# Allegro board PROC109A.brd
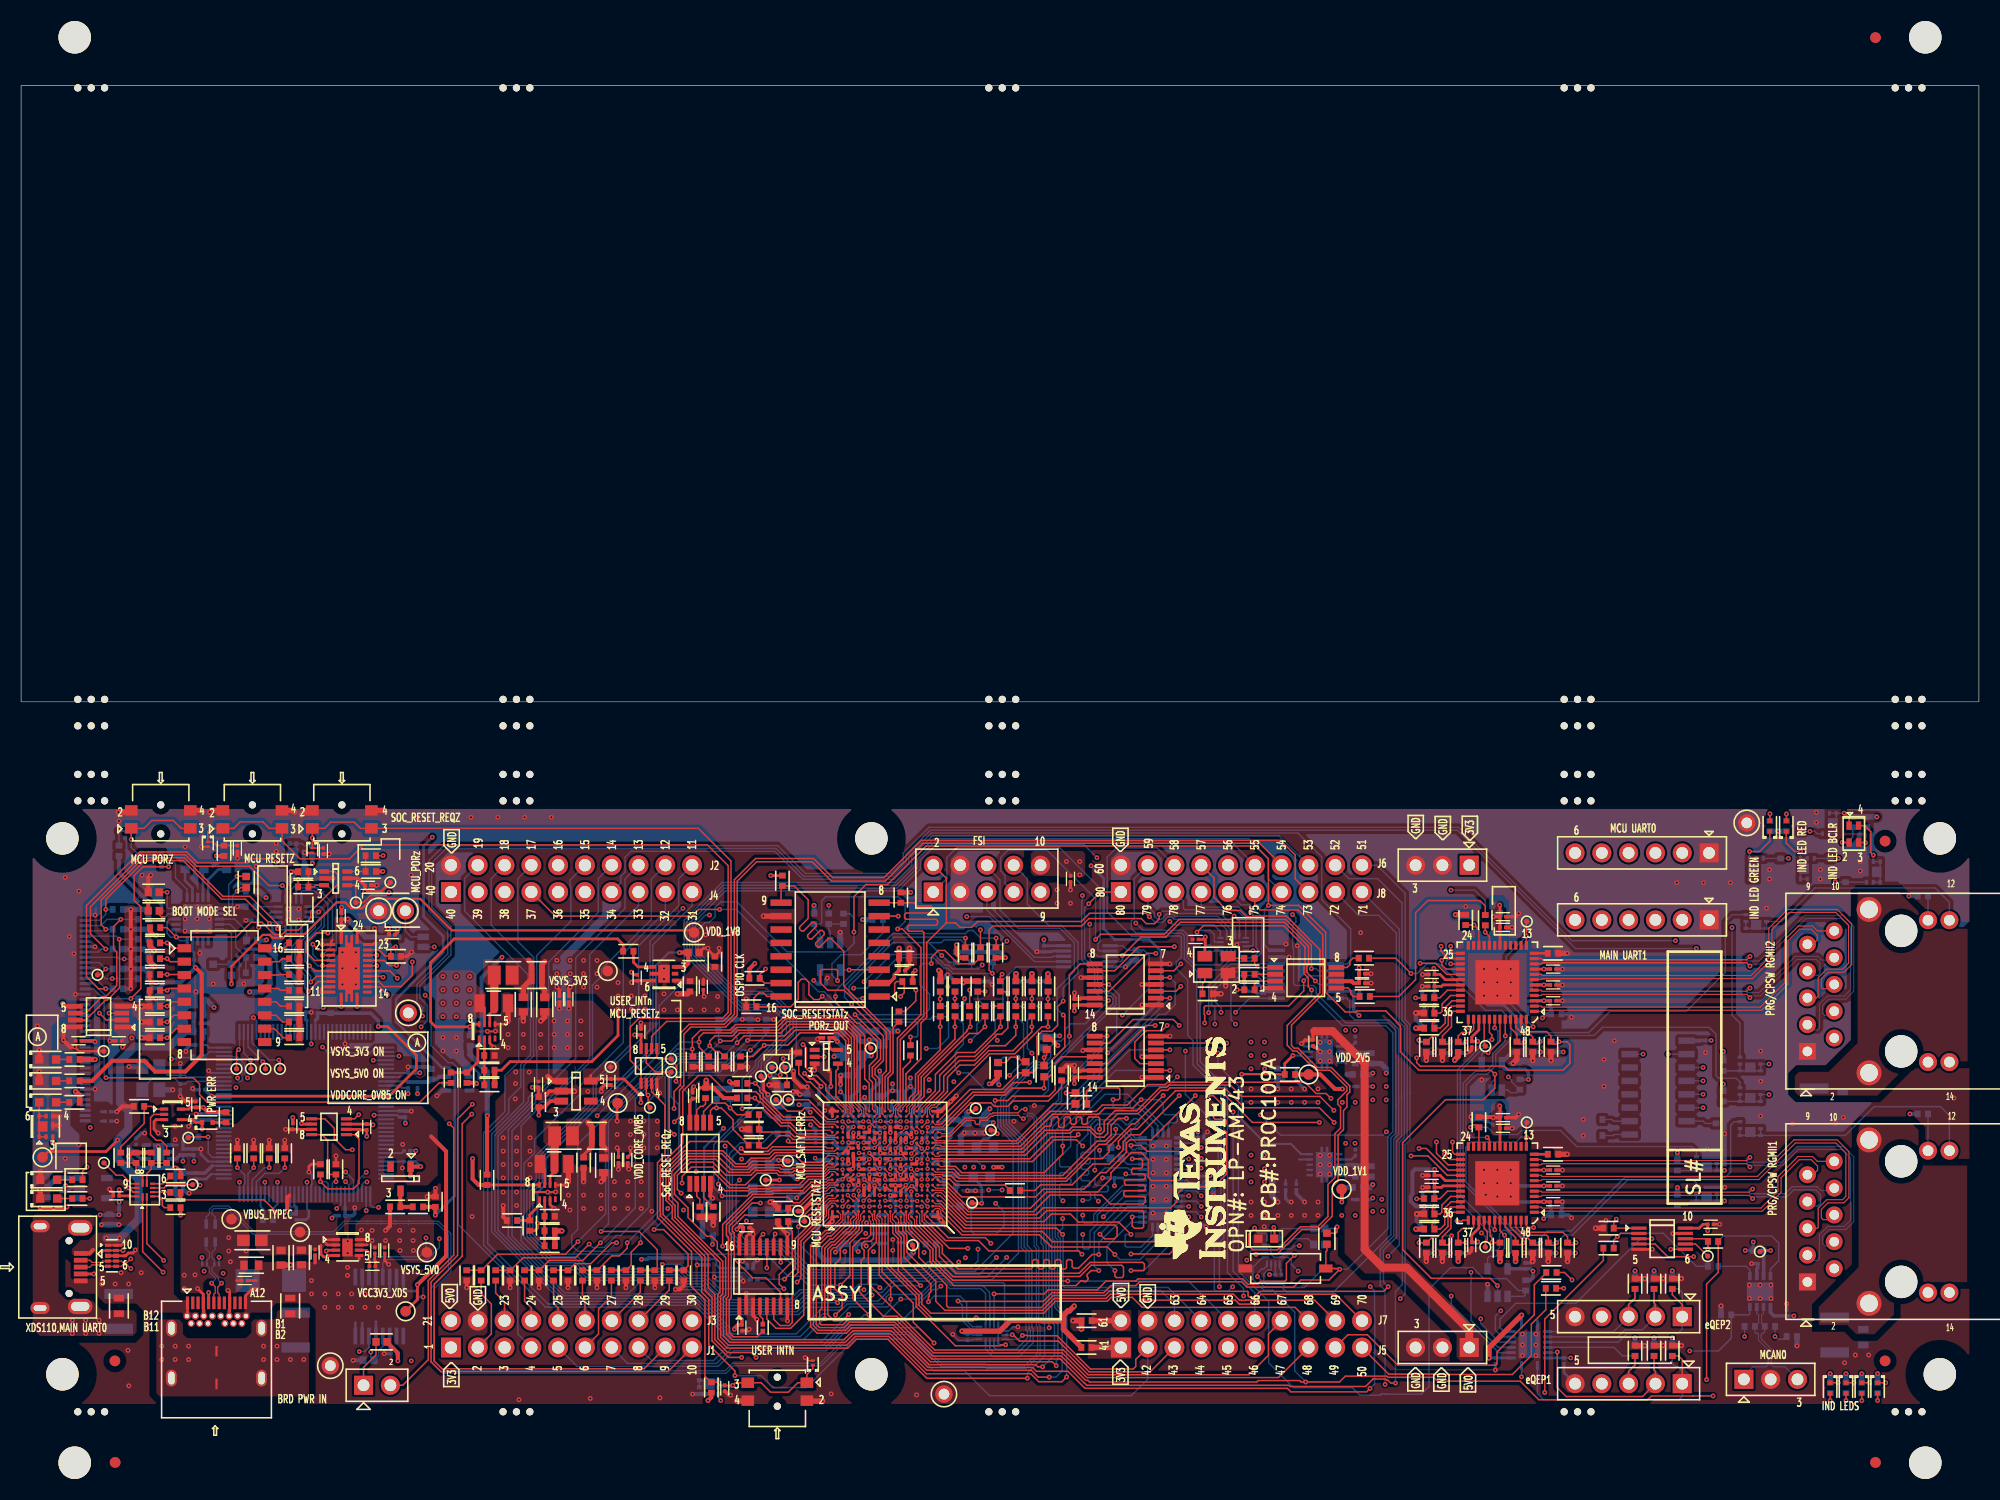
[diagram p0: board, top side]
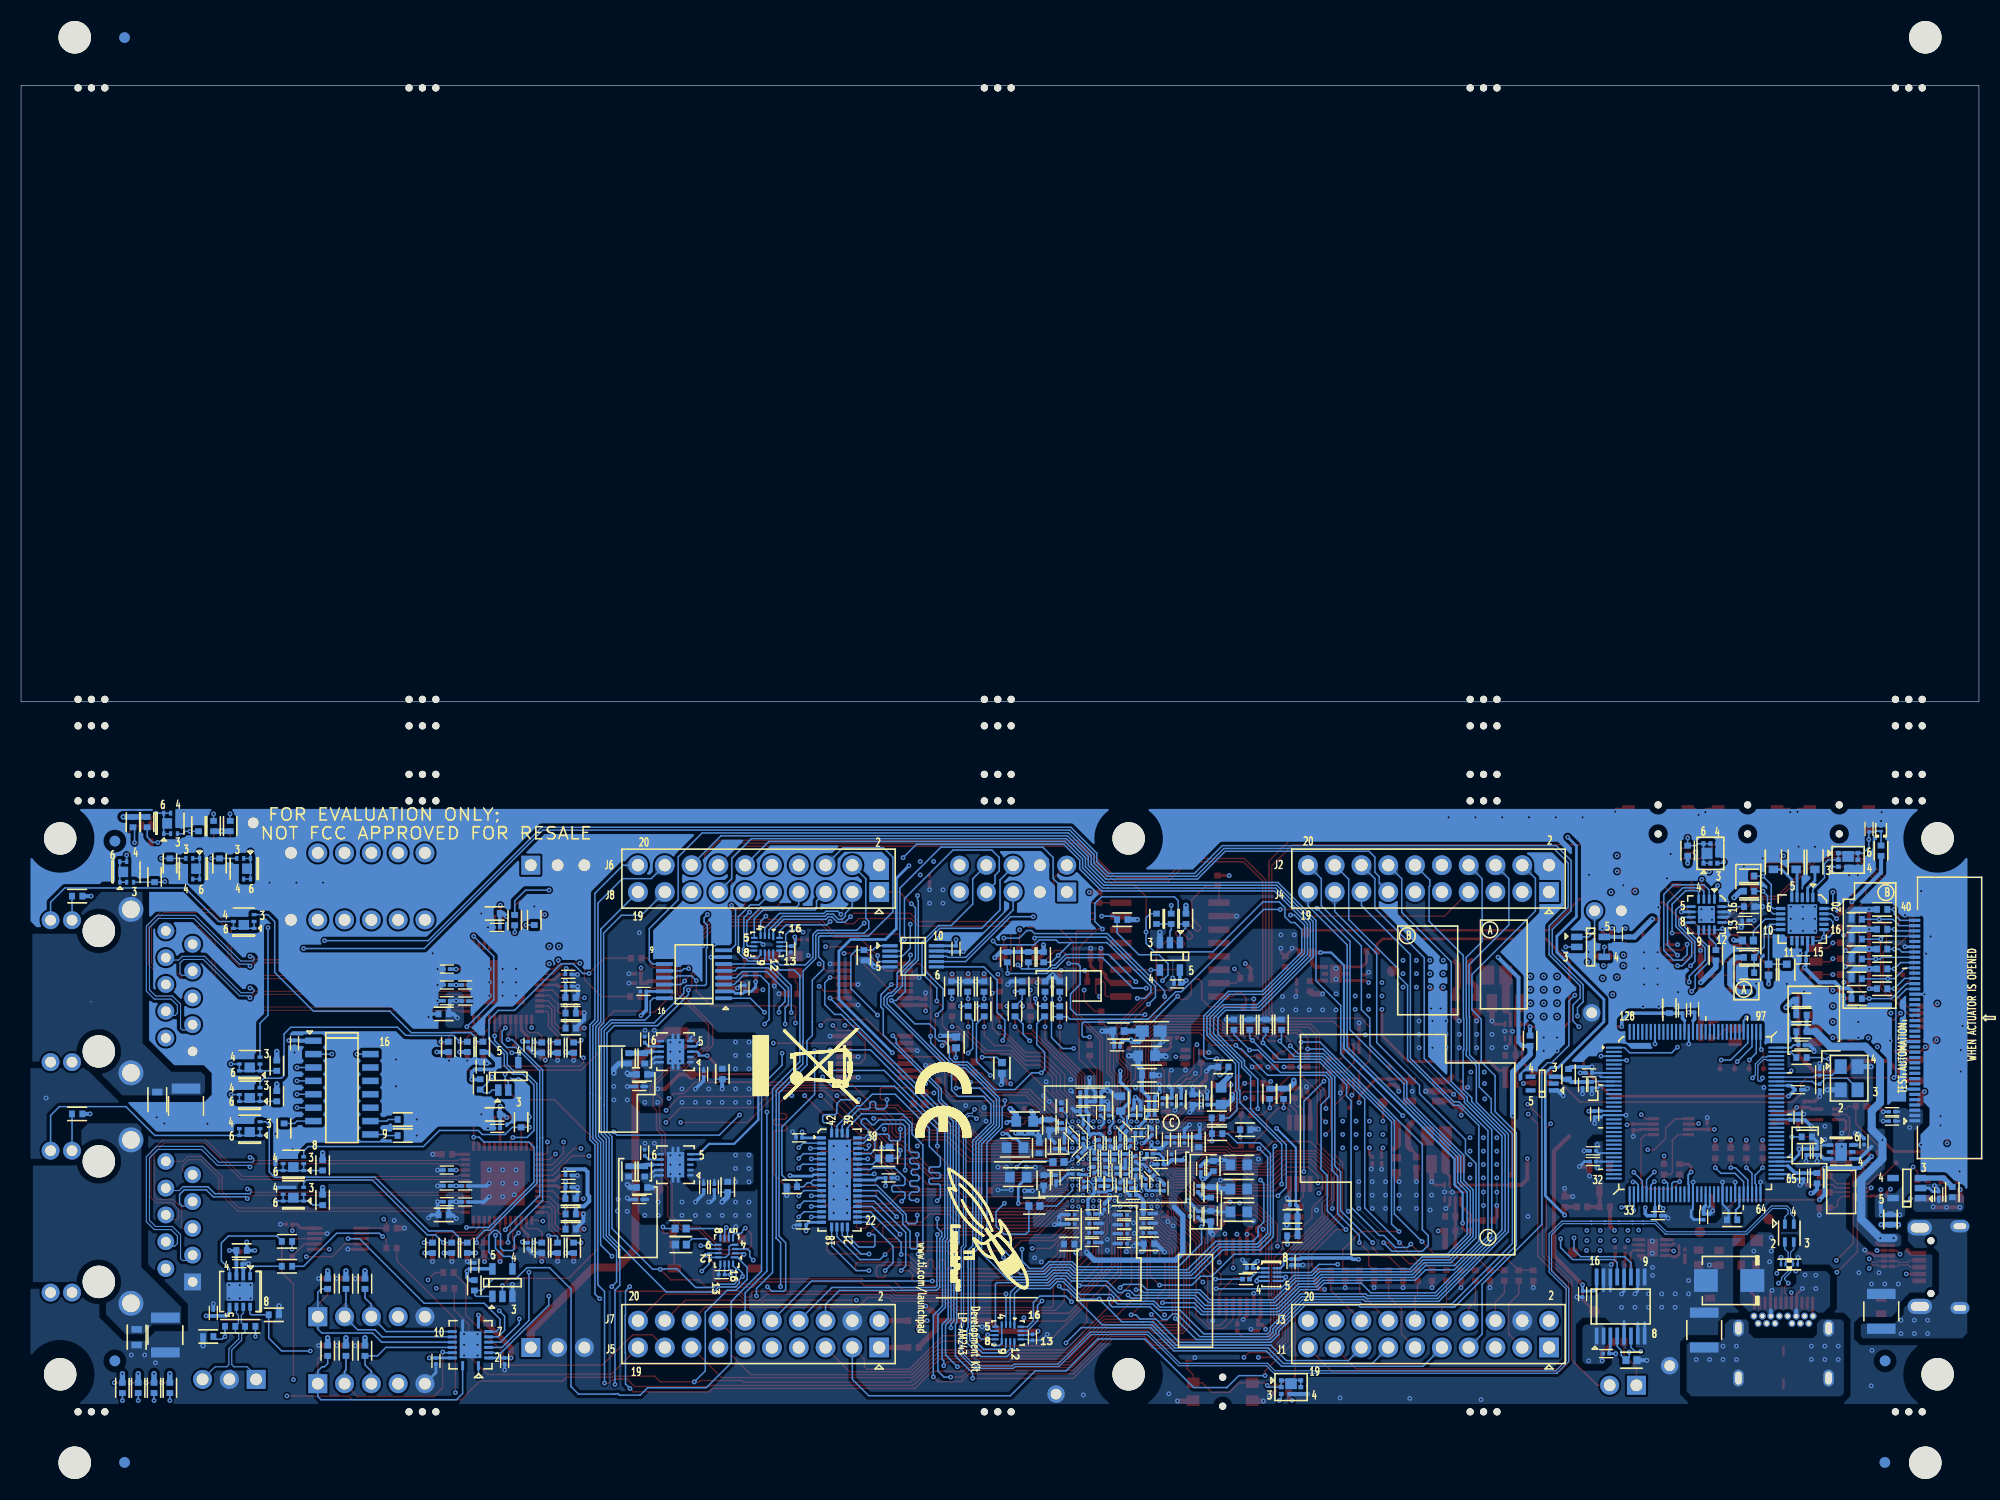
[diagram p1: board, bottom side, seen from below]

Outline 185.58 x 58.42 mm; copper layers: TOP, L02_GND1, L03_SIG1, L04_PWR1, L05_GND2, BOTTOM. Coordinates in mm from the lower left corner of the outline.
Outline path: 0,58.42 185.58,58.42 185.58,0 0,0 0,58.42

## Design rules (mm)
constraint set DEFAULT: min track width 0.135
net group MCAN0: nets MCAN0_H MCAN0_L
net group PRG1_CPSW_RGMII2_RX: nets PRG1_CPSW_RGMII2_RD0 PRG1_CPSW_RGMII2_RD1
net group PRG1_ETH3_D0M: nets PRG1_CPSW_ETH2_D0M PRG1_CPSW_ETH2_D0P
net group PRG1_ETH3_D1M: nets PRG1_CPSW_ETH2_D1M PRG1_CPSW_ETH2_D1P
net group TYPEC_DP: nets TYPEC_DN TYPEC_DP
net group USB0: nets USB0_DN USB0_DP
net group XDS_USB_D_NP: nets XDS_USB_D_N XDS_USB_D_P
net group CPSW_RGMII1_TD1: nets CPSW_RGMII1_TD1
net group CPSW_RGMII1_TX_CTL: nets CPSW_RGMII1_TX_CTL
net group PRG1_CPSW RGMII2_TX: nets PRG1_CPSW_RGMII2_TD0 PRG1_CPSW_RGMII2_TD1 PRG1_CPSW_RGMII2_TD2 PRG1_CPSW_RGMII2_TD3 PRG1_CPSW_RGMII2_TX_CTL
net group PRG1_CPSW_RGMII1_RXC: nets PRG1_CPSW_RGMII1_RXC
net group PRG1_CPSW_RGMII2_RXC: nets PRG1_CPSW_RGMII2_RXC
net group PRG1_CPSW_RGMII2_TXC: nets PRG1_CPSW_RGMII2_TXC
net group PWR: nets VDD_CORE_0V85 VDDA_1V8 VDDSHV_3V3
net group PWR\GND: nets VBAT_XDS VCC_5V0_CAN VDD_1V1_SS VDD_1V8_R VDD_2V5_PG VDD_CORE_0V85_R VDDA_3V3 VDDA_PLL0 VDDC_1V2_XDS VDDSHV_SDIO VMON_VSYS VSYS_3V3_R XDS_VREF

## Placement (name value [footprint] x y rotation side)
C1  1uF  [CAP0201_0-5]  20.5 -13.91 270 top
C2  1uF  [CAP0201_0-5]  28.65 -14.15 270 top
C3  0.1uF  [CAP0201_0-5]  99.47 -16.79 90 top
C4  0.1uF  [CAP0201_0-5]  32.87 -17.4 0 top
C5  0.1uF  [CAP0201_0-5]  30.34 -20.32 90 top
C6  0.1uF  [CAP0201_0-5]  140.46 -20.37 0 top
C7  0.1uF  [CAP0201_0-5]  140.46 -21.39 0 top
C8  0.1uF  [CAP0201_0-5]  35.15 -22.07 0 top
C9  0.1uF  [CAP0201_0-5]  111.33 -22.53 0 top
C10  4.7uF  [CAP0402_0-75]  83.72 -24.31 0 top
C11  0.1uF  [CAP0201_0-5]  145.23 -25.34 0 top
C12  0.1uF  [CAP0201_0-5]  83.49 -25.48 0 top
C13  1uF  [CAP0201_0-5]  127.11 -25.78 0 top
C14  0.01uF  [CAP0201_0-5]  133.7 -25.85 180 top
C15  1uF  [CAP0201_0-5]  58.4 -26.16 90 top
C16  0.1uF  [CAP0201_0-5]  127.11 -26.67 180 top
C17  0.01uF  [CAP0201_0-5]  145.23 -26.84 0 top
C18  2.2uF  [CAP0402_0-75]  63.4 -26.97 270 top
C19  0.1uF  [CAP0201_0-5]  133.7 -26.98 180 top
C20  0.1uF  [CAP0201_0-5]  64.67 -27.03 270 top
C21  0.1uF  [CAP0201_0-5]  51.03 -28.19 270 top
C22  0.1uF  [CAP0201_0-5]  51.92 -28.19 270 top
C23  0.01uF  [CAP0201_0-5]  145.23 -28.34 0 top
C24  0.1uF  [CAP0201_0-5]  99.84 -28.47 90 top
C25  4.7uF  [CAP1206_2]  44.81 -28.57 0 top
C26  22uF  [CAP0603_1]  47.6 -28.7 270 top
C27  47uF  [CAP0603_1]  49.64 -28.7 270 top
C28  100pF  [CAP0402_0-75]  63.68 -34.11 270 top
C29  0.1uF  [CAP0201_0-5]  58.75 -31.29 90 top
C30  0.1uF  [CAP0201_0-5]  76.33 -31.85 0 top
C31  0.1uF  [CAP0201_0-5]  5.44 -32.13 0 top
C32  0.1uF  [CAP0201_0-5]  9.25 -32.13 180 top
C33  100pF  [CAP0402_0-75]  65.18 -34.11 270 top
C34  0.1uF  [CAP0201_0-5]  137.51 -32.45 270 top
C35  100pF  [CAP0402_0-75]  66.69 -34.11 270 top
C36  100pF  [CAP0402_0-75]  68.19 -34.11 270 top
C37  0.1uF  [CAP0201_0-5]  99.84 -35.32 90 top
C38  1uF  [CAP0201_0-5]  55.91 -36.04 270 top
C39  1uF  [CAP0201_0-5]  49.05 -36.27 270 top
C40  120pF  [CAP0402_0-75]  44.39 -36.32 180 top
C41  0.1uF  [CAP0201_0-5]  63.65 -37.34 90 top
C42  0.1uF  [CAP0201_0-5]  16.56 -38.18 90 top
C43  0.1uF  [CAP0201_0-5]  140.46 -39.42 0 top
C44  0.1uF  [CAP0201_0-5]  25.76 -40.25 90 top
C45  0.1uF  [CAP0201_0-5]  32.77 -40.31 270 top
C46  0.1uF  [CAP0201_0-5]  140.46 -40.44 0 top
C47  100pF  [CAP0402_0-75]  69.45 -40.51 180 top
C48  0.1uF  [CAP0201_0-5]  56.62 -43.43 270 top
C49  0.1uF  [CAP0201_0-5]  57.51 -43.43 270 top
C50  10uF  [CAP0402_0-75]  53.32 -43.69 270 top
C51  4.7uF  [CAP1206_2]  50.53 -43.81 0 top
C52  47uF  [CAP0603_1]  55.22 -43.94 270 top
C53  0.1uF  [CAP0201_0-5]  145.23 -44.39 0 top
C54  0.01uF  [CAP0201_0-5]  133.7 -44.9 180 top
C55  0.01uF  [CAP0201_0-5]  145.23 -45.89 0 top
C56  0.1uF  [CAP0201_0-5]  133.7 -46.03 180 top
C57  0.1uF  [CAP0201_0-5]  9.02 -46.84 180 top
C58  0.01uF  [CAP0201_0-5]  145.23 -47.39 0 top
C59  0.1uF  [CAP0201_0-5]  160.15 -49.53 0 top
C60  0.1uF  [CAP0201_0-5]  68.73 -49.86 0 top
C61  0.1uF  [CAP0201_0-5]  137.51 -51.5 270 top
C62  120pF  [CAP0402_0-75]  50.11 -51.56 180 top
C63  0.1uF  [CAP0201_0-5]  33.53 -52.02 270 top
C64  1uF  [CAP0201_0-5]  34.47 -52.02 270 top
C65  0.1uF  [CAP0201_0-5]  27.86 -52.2 270 top
C66  10uF  [CAP0603_1]  26.57 -52.68 270 top
C67  10uF  [CAP0603_1]  24.64 -52.7 270 top
C68  10uF  [CAP0603_1]  21.82 -53.42 0 top
C69  0.01uF  [CAP0201_0-5]  33.3 -53.52 0 top
C70  0.1uF  [CAP0201_0-5]  21.19 -54.86 0 top
C71  1000pF  [CAP0402_0-75]  152.98 -55.17 90 top
C72  1000pF  [CAP0402_0-75]  154.79 -55.17 90 top
C73  1000pF  [CAP0402_0-75]  156.51 -55.17 90 top
C74  0.1uF  [CAP0201_0-5]  68.33 -59.33 270 top
C75  1000pF  [CAP0402_0-75]  152.98 -61.52 90 top
C76  1000pF  [CAP0402_0-75]  154.79 -61.52 90 top
C77  1000pF  [CAP0402_0-75]  156.51 -61.52 90 top
C78  1uF  [CAP0201_0-5]  66.7 -65.07 270 top
C79  1uF  [CAP0201_0-5]  10.42 -12.04 90 bottom
C80  2400pF  [CAP0603_1]  19.48 -15.19 90 bottom
C81  2400pF  [CAP0603_1]  17.32 -15.19 90 bottom
C82  2400pF  [CAP0603_1]  15.54 -15.19 90 bottom
C84  10uF  [CAP0402_0-75]  140.7 -20.07 0 bottom
C85  0.1uF  [CAP0201_0-5]  22.15 -20.73 180 bottom
C86  1uF  [CAP0201_0-5]  140.49 -21.39 0 bottom
C88  0.1uF  [CAP0201_0-5]  34.17 -22.01 90 bottom
C90  0.1uF  [CAP0201_0-5]  96.96 -23.41 270 bottom
C91  0.1uF  [CAP0201_0-5]  16.66 -24.46 0 bottom
C92  0.1uF  [CAP0201_0-5]  145.23 -25.34 0 bottom
C93  1uF  [CAP0201_0-5]  133.71 -25.83 180 bottom
C94  0.1uF  [CAP0201_0-5]  76.02 -26.75 0 bottom
C95  0.1uF  [CAP0201_0-5]  145.23 -26.84 0 bottom
C96  1uF  [CAP0201_0-5]  143.49 -26.85 180 bottom
C97  1uF  [CAP0201_0-5]  133.68 -26.97 180 bottom
C98  10uF  [CAP0402_0-75]  133.51 -28.04 180 bottom
C99  1uF  [CAP0201_0-5]  145.23 -28.34 0 bottom
C100  1uF  [CAP0201_0-5]  143.49 -28.37 180 bottom
C101  1000pF  [CAP1210_1-5]  169.95 -38.32 270 bottom
C102  2.2uF  [CAP0402_0-75]  29.34 -29.03 90 bottom
C103  0.1uF  [CAP0201_0-5]  116.97 -27.18 90 bottom
C104  0.1uF  [CAP0201_0-5]  26.95 -29.16 90 bottom
C105  0.01uF  [CAP0201_0-5]  28.1 -29.24 90 bottom
C106  0.1uF  [CAP0201_0-5]  126.59 -27.46 0 bottom
C107  10uF  [CAP0402_0-75]  145.52 -29.59 0 bottom
C108  100pF  [CAP0402_0-75]  66.11 -30.61 90 bottom
C109  4.7uF  [CAP0402_0-75]  81.56 -31.22 0 bottom
C110  100pF  [CAP0402_0-75]  67.61 -30.61 90 bottom
C111  0.01uF  [CAP0201_0-5]  126.47 -32.02 90 bottom
C112  0.1uF  [CAP0201_0-5]  159.66 -32.38 90 bottom
C113  1uF  [CAP0201_0-5]  137.52 -32.51 270 bottom
C114  0.1uF  [CAP0201_0-5]  16.82 -32.54 180 bottom
C116  0.01uF  [CAP0201_0-5]  81.69 -32.72 0 bottom
C117  100pF  [CAP0402_0-75]  69.11 -30.61 90 bottom
C118  100pF  [CAP0402_0-75]  70.62 -30.61 90 bottom
C119  0.1uF  [CAP0201_0-5]  142.06 -34.57 90 bottom
C120  30pF  [CAP0201_0-5]  15.09 -35.13 270 bottom
C121  0.1uF  [CAP0201_0-5]  36.96 -35.18 0 bottom
C122  0.1uF  [CAP0201_0-5]  120.88 -35.28 270 bottom
C123  1uF  [CAP0201_0-5]  122.45 -32.33 270 top
C124  4.7uF  [CAP0402_0-75]  119.11 -35.28 270 bottom
C125  10uF  [CAP0402_0-75]  126.72 -35.33 0 bottom
C126  4.7uF  [CAP0402_0-75]  78.84 -35.41 180 bottom
C128  0.01uF  [CAP0201_0-5]  37.57 -36.32 270 bottom
C129  0.1uF  [CAP0201_0-5]  36.68 -36.32 270 bottom
C130  0.1uF  [CAP0201_0-5]  126.97 -36.47 0 bottom
C131  30pF  [CAP0201_0-5]  15.09 -36.53 90 bottom
C132  1uF  [CAP0201_0-5]  17.14 -36.78 180 bottom
C133  0.1uF  [CAP0201_0-5]  84.89 -37.01 0 bottom
C134  0.1uF  [CAP0201_0-5]  83.47 -37.01 180 bottom
C135  0.1uF  [CAP0201_0-5]  78.41 -37.49 180 bottom
C136  10uF  [CAP0402_0-75]  74.52 -37.72 90 bottom
C137  0.1uF  [CAP0201_0-5]  77.39 -37.85 90 bottom
C138  0.1uF  [CAP0201_0-5]  76.5 -37.85 90 bottom
C139  0.1uF  [CAP0201_0-5]  75.62 -37.85 90 bottom
C140  0.1uF  [CAP0201_0-5]  84.89 -37.9 0 bottom
C141  0.1uF  [CAP0201_0-5]  83.47 -37.9 180 bottom
C142  0.1uF  [CAP0201_0-5]  73.15 -37.91 90 bottom
C143  3.3uF  [CAP0603_1]  81.36 -38.1 90 bottom
C144  0.1uF  [CAP0201_0-5]  78.41 -38.25 180 bottom
C145  0.1uF  [CAP0201_0-5]  84.89 -38.81 0 bottom
C146  0.1uF  [CAP0201_0-5]  8.23 -38.86 0 bottom
C147  0.1uF  [CAP0201_0-5]  80.21 -38.91 90 bottom
C148  0.01uF  [CAP0201_0-5]  79.45 -38.91 90 bottom
C149  1uF  [CAP0201_0-5]  83.26 -38.94 90 bottom
C150  1uF  [CAP0201_0-5]  82.5 -38.94 90 bottom
C151  0.01uF  [CAP0201_0-5]  36.42 -39.09 270 bottom
C152  10uF  [CAP0402_0-75]  140.7 -39.12 0 bottom
C153  0.01uF  [CAP0201_0-5]  78.41 -39.19 180 bottom
C154  1uF  [CAP0201_0-5]  17.14 -39.37 90 bottom
C155  0.1uF  [CAP0201_0-5]  8.23 -39.75 0 bottom
C156  4.7uF  [CAP0402_0-75]  88.11 -40.11 270 bottom
C157  0.1uF  [CAP0201_0-5]  86.89 -40.21 270 bottom
C158  0.1uF  [CAP0201_0-5]  84.71 -40.26 45 bottom
C159  1uF  [CAP0201_0-5]  140.44 -40.44 0 bottom
C160  0.1uF  [CAP0201_0-5]  81 -40.49 225 bottom
C161  100pF  [CAP0402_0-75]  69.55 -40.56 180 bottom
C162  0.1uF  [CAP0201_0-5]  78.36 -40.77 90 bottom
C163  0.1uF  [CAP0201_0-5]  79.68 -40.84 180 bottom
C165  0.1uF  [CAP0201_0-5]  86.03 -41 45 bottom
C166  0.1uF  [CAP0201_0-5]  111.83 -41.34 0 bottom
C167  0.1uF  [CAP0201_0-5]  77.01 -41.53 90 bottom
C168  0.1uF  [CAP0201_0-5]  76.26 -41.53 90 bottom
C169  0.1uF  [CAP0201_0-5]  75.32 -41.53 90 bottom
C170  1uF  [CAP0201_0-5]  10.9 -41.68 90 bottom
C171  4.7uF  [CAP0402_0-75]  73.97 -41.73 90 bottom
C172  0.1uF  [CAP0201_0-5]  81.39 -41.81 270 bottom
C173  1uF  [CAP0201_0-5]  83.39 -41.83 270 bottom
C174  0.01uF  [CAP0201_0-5]  80.42 -41.83 90 bottom
C175  0.1uF  [CAP0201_0-5]  82.35 -41.86 270 bottom
C176  0.1uF  [CAP0201_0-5]  87.6 -42.09 90 bottom
C177  0.01uF  [CAP0201_0-5]  86.69 -42.09 90 bottom
C178  0.01uF  [CAP0201_0-5]  84.89 -41.66 270 bottom
C179  4.7uF  [CAP0402_0-75]  89.08 -42.29 90 bottom
C180  1uF  [CAP0201_0-5]  36.58 -42.57 0 bottom
C181  0.1uF  [CAP0201_0-5]  16.36 -42.67 270 bottom
C182  1uF  [CAP0201_0-5]  15.35 -42.67 270 bottom
C183  0.01uF  [CAP0201_0-5]  126.47 -42.74 90 bottom
C184  0.01uF  [CAP0201_0-5]  78.59 -42.85 180 bottom
C185  0.01uF  [CAP0201_0-5]  83.87 -43.08 90 bottom
C186  0.1uF  [CAP0201_0-5]  82.87 -43.15 270 bottom
C187  1uF  [CAP0201_0-5]  81.92 -43.15 270 bottom
C188  0.01uF  [CAP0201_0-5]  80.91 -43.15 270 bottom
C189  0.1uF  [CAP0201_0-5]  76.53 -43.18 270 bottom
C190  0.01uF  [CAP0201_0-5]  79.91 -43.33 270 bottom
C191  0.01uF  [CAP0201_0-5]  36.58 -43.59 0 bottom
C192  1uF  [CAP0201_0-5]  77.57 -43.86 180 bottom
C193  4.7uF  [CAP0402_0-75]  72.57 -44.02 270 bottom
C194  0.1uF  [CAP0201_0-5]  73.76 -44.27 270 bottom
C196  1uF  [CAP0201_0-5]  83.86 -44.37 270 bottom
C197  0.1uF  [CAP0201_0-5]  145.23 -44.39 0 bottom
C198  0.01uF  [CAP0201_0-5]  82.85 -44.4 270 bottom
C199  0.1uF  [CAP0201_0-5]  81.79 -44.45 90 bottom
C200  0.01uF  [CAP0201_0-5]  80.92 -44.49 90 bottom
C201  0.1uF  [CAP0201_0-5]  79.91 -44.62 270 bottom
C202  0.1uF  [CAP0201_0-5]  78.41 -44.7 45 bottom
C203  0.01uF  [CAP0201_0-5]  85.62 -44.75 0 bottom
C204  0.1uF  [CAP0201_0-5]  87.48 -45.16 270 bottom
C205  0.1uF  [CAP0201_0-5]  85.24 -42.93 135 bottom
C206  4.7uF  [CAP0402_0-75]  88.65 -45.36 270 bottom
C207  1uF  [CAP0201_0-5]  133.7 -44.9 180 bottom
C208  0.1uF  [CAP0201_0-5]  16.62 -44.96 270 bottom
C209  0.1uF  [CAP0201_0-5]  103.35 -45.14 180 bottom
C210  0.01uF  [CAP0201_0-5]  78.97 -45.52 270 bottom
C211  0.1uF  [CAP0201_0-5]  83.32 -45.64 270 bottom
C212  0.1uF  [CAP0201_0-5]  82.5 -45.64 270 bottom
C213  0.1uF  [CAP0201_0-5]  84.86 -45.75 270 bottom
C214  0.1uF  [CAP0201_0-5]  80.39 -45.82 90 bottom
C215  0.1uF  [CAP0201_0-5]  81.41 -45.87 90 bottom
C216  0.1uF  [CAP0201_0-5]  145.23 -45.89 0 bottom
C217  1uF  [CAP0201_0-5]  143.49 -45.9 180 bottom
C218  0.1uF  [CAP0201_0-5]  120.88 -46 270 bottom
C219  1uF  [CAP0201_0-5]  119.87 -46 270 bottom
C220  4.7uF  [CAP0402_0-75]  118.6 -46 270 bottom
C221  1uF  [CAP0201_0-5]  133.7 -46.03 180 bottom
C222  10uF  [CAP0402_0-75]  126.72 -46.05 0 bottom
C223  1uF  [CAP0201_0-5]  77.24 -46.08 270 bottom
C224  0.1uF  [CAP0201_0-5]  74.02 -46.18 270 bottom
C225  4.7uF  [CAP0402_0-75]  72.82 -46.51 270 bottom
C226  1uF  [CAP0201_0-5]  3.81 -46.72 90 bottom
C227  0.1uF  [CAP0201_0-5]  80.19 -46.79 0 bottom
C228  10uF  [CAP0402_0-75]  133.51 -47.09 180 bottom
C229  0.1uF  [CAP0201_0-5]  126.97 -47.19 0 bottom
C230  1uF  [CAP0201_0-5]  145.23 -47.39 0 bottom
C231  1uF  [CAP0201_0-5]  143.49 -47.42 180 bottom
C232  0.1uF  [CAP0201_0-5]  65.02 -47.7 0 bottom
C233  1uF  [CAP0201_0-5]  82.88 -47.85 270 bottom
C234  0.01uF  [CAP0201_0-5]  78.92 -48.52 180 bottom
C235  0.1uF  [CAP0201_0-5]  84.05 -48.54 180 bottom
C236  0.1uF  [CAP0201_0-5]  74.02 -48.59 270 bottom
C237  0.1uF  [CAP0201_0-5]  85.98 -48.62 0 bottom
C238  10uF  [CAP0402_0-75]  145.52 -48.64 0 bottom
C239  0.1uF  [CAP0201_0-5]  81.03 -48.64 0 bottom
C240  0.01uF  [CAP0201_0-5]  30.43 -48.72 180 bottom
C241  4.7uF  [CAP0402_0-75]  72.82 -48.77 270 bottom
C242  0.01uF  [CAP0201_0-5]  26.09 -48.82 270 bottom
C243  10uF  [CAP0402_0-75]  8.38 -49.08 270 bottom
C244  0.1uF  [CAP0201_0-5]  78.92 -49.43 180 bottom
C245  0.1uF  [CAP0201_0-5]  84.05 -49.45 180 bottom
C246  0.1uF  [CAP0201_0-5]  85.98 -49.5 0 bottom
C247  0.1uF  [CAP0201_0-5]  81.03 -49.58 0 bottom
C248  0.1uF  [CAP0201_0-5]  111.45 -49.59 0 bottom
C249  0.1uF  [CAP0201_0-5]  84.05 -50.34 180 bottom
C250  0.1uF  [CAP0201_0-5]  78.92 -50.34 180 bottom
C251  0.1uF  [CAP0201_0-5]  81.03 -50.42 0 bottom
C252  1000pF  [CAP1210_1-5]  171.91 -60.03 270 bottom
C253  0.01uF  [CAP0201_0-5]  84.07 -51.26 180 bottom
C254  0.1uF  [CAP0201_0-5]  81.03 -51.35 0 bottom
C255  4.7uF  [CAP0402_0-75]  78.66 -51.38 180 bottom
C256  1uF  [CAP0201_0-5]  137.52 -51.56 270 bottom
C257  0.1uF  [CAP0201_0-5]  164.89 -53.27 180 bottom
C258  0.1uF  [CAP0201_0-5]  142.57 -53.47 90 bottom
C259  0.1uF  [CAP0201_0-5]  69.11 -53.71 0 bottom
C260  0.1uF  [CAP0201_0-5]  65.2 -53.11 270 bottom
C262  0.1uF  [CAP0201_0-5]  37.57 -56.15 270 bottom
C263  1000pF  [CAP1210_1-5]  9.25 -57.78 90 bottom
C265  0.1uF  [CAP0201_0-5]  167.36 -57.94 270 bottom
C266  1000pF  [CAP1210_1-5]  26.04 -59.56 90 bottom
C267  4700pF  [CAP0402_0-75]  167.84 -60.17 0 bottom
C268  0.1uF  [CAP0201_0-5]  35.33 -61.8 180 bottom
C269  0.1uF  [CAP0201_0-5]  146.26 -62.48 270 bottom
C270  0.1uF  [CAP0201_0-5]  139.75 -62.48 270 bottom
C271  0.1uF  [CAP0201_0-5]  89.71 -60.25 90 bottom
C272  0.1uF  [CAP0201_0-5]  112.62 -23.44 90 bottom
C273  0.1uF  [CAP0201_0-5]  119.18 -54.31 180 bottom
D1  TPD1E01B04DPLT  [DIO_DFN0201_0-4]  17.7 -13.51 270 top
D2  TPD1E01B04DPLT  [DIO_DFN0201_0-4]  27.61 -14.1 270 top
D3  BZX84C6V8LT1G  [SOT23-123_1-2]  35.97 -45.22 270 top
D4  TPD1E01B04DPLT  [DIO_DFN0201_0-4]  75.05 -62.68 90 top
D5  TPD1E01B04DPLT  [DIO_DFN0201_0-4]  9.28 -12.04 90 bottom
D6  TPD1E01B04DPLT  [DIO_DFN0201_0-4]  18.54 -53.34 0 bottom
D7  TPD1E01B04DPLT  [DIO_DFN0201_0-4]  17.4 -53.34 180 bottom
D8  SMBJ6.5CA  [DIO_SMB_2-7]  23.67 -54.86 0 bottom
FB1  120E  [IND0603_1#2]  78.46 -31.22 0 bottom
FB2  120E  [IND0603_1]  78.89 -33.56 0 bottom
FB3  120E  [IND0603_1]  71.83 -37.39 270 bottom
FB4  120E  [IND0603_1]  90.45 -39.78 180 bottom
FB5  120E  [IND0603_1]  91.36 -42.27 180 bottom
FB6  120E  [IND0603_1]  70.15 -43.89 0 bottom
FB7  120E  [IND0603_1]  91.06 -45.06 180 bottom
FB8  120E  [IND0603_1]  70.15 -46.18 0 bottom
FB9  120E  [IND0603_1]  70.15 -48.36 0 bottom
FL1  70E  [EMIFIL_BLM18B_0603_0-7]  21.92 -51.05 0 top
J1  RECP_2X10  [RECPT_2X10_CRD-081413-A_S_T_8-6]  40.75 -61.21 0 bottom
J2  RECP_2X10  [RECPT_2X10_CRD-081413-A_S_T_8-6]  40.75 -18.03 0 bottom
J5  RECP_2X10  [RECPT_2X10_CRD-081413-A_S_T_8-6]  104.25 -61.21 0 bottom
J6  RECP_2X10  [RECPT_2X10_CRD-081413-A_S_T_8-6]  104.25 -18.03 0 bottom
J9  HDR_1X3  [HDR_1X3_100_S_T]  137.27 -61.21 0 top
J10  CON_USB-C_24_F  [CON_USBC24_6327233_S_R_S_3-1]  18.52 -62.8 0 top
J11  HDR_1X3  [HDR_1X3_100_S_T]  163.3 -64.24 180 top
J12  HDR_1X5  [HDR_1X5_61300511121_S_T_8-6]  157.46 -64.64 0 top
J13  HDR_1X6  [HDR_1X6_61300611121_S_T_8-6]  160 -20.68 0 top
J14  HDR_1X3  [HDR_1X3_100_S_T]  137.27 -15.49 0 top
J15  CON_FLEX_1X40_687140183622  [CON_FLEX1X40_687140183622_S_R_S_1-3]  3.67 -29.97 90 bottom
J16  HDR_2X5  [HDR_2X5_61301021121_S_T_8-6]  86.47 -18.03 0 top
J17  HDR_1X6  [HDR_1X6_61300611121_S_T_8-6]  160 -14.33 0 top
J18  CON_RJ45-14_LPJG16314A4NL  [CON_RJ45-14_LPJG16314A4NL_S_R_T_13-6]  169.32 -33.15 90 top
J19  CON_RJ45-14_LPJG16314A4NL  [CON_RJ45-14_LPJG16314A4NL_S_R_T_13-6]  169.32 -55 90 top
J20  CON_MUSB-B_5_F  [CON_MUSBB5_629105150521_S_R_S_2-7]  2.7 -53.59 270 top
J21  HDR_1X5  [HDR_1X5_61300511121_S_T_8-6]  157.46 -58.29 0 top
J22  HDR_1X2  [HDR_1X2_61300211121_S_T_8-6]  32.46 -64.8 180 top
L1  0.47uH  [IND0806_1-2]  45.7 -25.91 0 top
L2  0.47uH  [IND0806_1-2]  51.41 -41.15 0 top
L3  90E  [IND4_DLW21H_90X60_SMD_1-4]  17.97 -50.37 270 bottom
LD1  150040VS73220  [LED_150040GS73220_40X20_SMD_0-4]  167.32 -11.79 90 top
LD2  150040RS73220  [LED_150040GS73220_40X20_SMD_0-4]  165.76 -11.78 90 top
LD3  150066RV54050  [LED4_150066RV54050_70X60_SMD_0-7]  173.72 -12.54 270 top
LD6  150060VS75000  [LED_150060SS75000_70X40_SMD_0-8]  2.52 -33.91 0 top
LD7  150060VS75000  [LED_150060SS75000_70X40_SMD_0-8]  2.52 -35.94 0 top
LD8  150060VS75000  [LED_150060SS75000_70X40_SMD_0-8]  2.52 -37.97 0 top
LD9  150040RS73220  [LED_150040GS73220_40X20_SMD_0-4]  17.65 -39.88 0 top
LD10  150060RS75000  [LED_150060SS75000_70X40_SMD_0-8]  2.62 -45.31 0 top
LD11  150060VS75000  [LED_150060SS75000_70X40_SMD_0-8]  2.62 -47.09 0 top
LD12  150040VS73220  [LED_150040GS73220_40X20_SMD_0-4]  171.48 -65.05 270 top
LD13  150040VS73220  [LED_150040GS73220_40X20_SMD_0-4]  172.98 -65.05 270 top
LD14  150040VS73220  [LED_150040GS73220_40X20_SMD_0-4]  174.48 -65.05 270 top
LD15  150040VS73220  [LED_150040GS73220_40X20_SMD_0-4]  175.98 -65.05 270 top
LD17  LTST-C190AKT  [LED_0603]  118.03 -50.9 0 top
NOREF  -  [unnamed]  178.91 -68.56 0 top
NOREF#2  -  [unnamed#2]  181.88 -12.95 180 top
NOREF#3  -  [#3]  88.62 -77.98 0 top
NOREF#4  -  [#3]  0 -74.68 90 top
NOREF#5  -  [unnamed#2]  176.69 -13.21 180 top
NOREF#6  -  [#3]  16.76 28.83 0 top
NOREF#7  -  [#3]  -357.68 263.52 0 top
NOREF#8  -  [unnamed]  147.54 -68.56 0 top
NOREF#9  -  [#3]  -351.92 -39.03 0 top
NOREF#10  -  [unnamed]  46.95 59.45 180 top
NOREF#11  -  [unnamed#2]  180.5 -72.14 180 top
NOREF#12  -  [unnamed]  6.64 -68.56 0 top
NOREF#13  -  [unnamed#2]  181.88 -63.75 90 top
NOREF#14  -  [unnamed#4]  147.54 -1.03 0 top
NOREF#15  -  [unnamed#2]  176.69 -62.48 180 top
NOREF#16  -  [unnamed]  93 -68.56 0 top
NOREF#17  -  [unnamed#2]  8.89 -62.48 0 top
NOREF#18  -  [unnamed#2]  8.92 -72.11 0 top
NOREF#19  -  [unnamed#2]  80.6 -63.75 90 top
NOREF#20  -  [unnamed]  6.64 59.45 180 top
NOREF#21  -  [unnamed#2]  3.92 -63.75 0 top
NOREF#22  -  [unnamed#4]  46.95 -8.14 0 top
NOREF#23  -  [unnamed]  93 59.45 180 top
NOREF#24  -  [unnamed#4]  6.64 -8.14 0 top
NOREF#25  -  [unnamed#2]  80.6 -12.95 180 top
NOREF#26  -  [unnamed]  46.95 -68.56 0 top
NOREF#27  -  [unnamed]  147.54 59.45 180 top
NOREF#28  -  [#3]  0 -7.11 90 top
NOREF#29  -  [#3]  -345.01 -90.78 0 top
NOREF#30  -  [unnamed#4]  178.91 -8.14 0 top
NOREF#31  -  [unnamed#2]  175.78 -72.11 0 top
NOREF#32  -  [unnamed#4]  178.91 -1.03 0 top
NOREF#33  -  [unnamed#2]  5.08 62.99 180 top
NOREF#34  -  [unnamed#2]  175.78 62.97 0 top
NOREF#35  -  [#3]  0 -2.03 90 top
NOREF#36  -  [unnamed#2]  5.08 -72.14 180 top
NOREF#37  -  [#3]  0 -67.56 90 top
NOREF#38  -  [unnamed#4]  93 -1.03 0 top
NOREF#39  -  [unnamed#4]  93 -8.14 0 top
NOREF#40  -  [unnamed]  178.91 59.45 180 top
NOREF#41  -  [unnamed#4]  147.54 -8.14 0 top
NOREF#42  -  [unnamed#4]  6.64 -1.03 180 top
NOREF#43  -  [unnamed#4]  46.95 -1.03 0 top
NOREF#44  -  [#3]  0 -67.56 0 top
NOREF#45  -  [unnamed#2]  3.92 -12.95 270 top
NOREF#46  -  [#3]  0 60.45 90 top
NOREF#47  -  [unnamed#2]  175.78 62.97 180 bottom
NOREF#48  -  [unnamed#2]  176.69 -62.48 0 bottom
NOREF#49  -  [unnamed#2]  8.89 -62.48 0 bottom
NOREF#50  -  [unnamed#2]  8.92 -72.11 180 bottom
NOREF#51  -  [unnamed#2]  175.78 -72.11 180 bottom
NOREF#52  -  [unnamed#2]  180.5 62.99 0 bottom
NOREF#53  -  [unnamed#2]  176.69 -13.21 180 bottom
Q3  CSD16301Q2  [WSON6_CSD13202Q2_80X80_0-8]  2.36 -40.26 90 top
Q4  CSD16301Q2  [WSON6_CSD13202Q2_80X80_0-8]  171.41 -11.53 90 bottom
Q5  CSD16301Q2  [WSON6_CSD13202Q2_80X80_0-8]  164.49 -15.82 270 bottom
Q6  CSD16301Q2  [WSON6_CSD13202Q2_80X80_0-8]  169.31 -15.82 270 bottom
Q7  CSD25310Q2  [SON6_CSD17313Q2_80X80]  25.45 -14.38 180 bottom
Q8  CSD25310Q2  [SON6_CSD17313Q2_80X80]  12.4 -14.99 270 bottom
Q9  CSD16301Q2  [WSON6_CSD13202Q2_80X80_0-8]  175.58 -16.13 90 bottom
Q10  CSD16301Q2  [WSON6_CSD13202Q2_80X80_0-8]  164.47 -20.83 0 bottom
Q11  CSD16301Q2  [WSON6_CSD13202Q2_80X80_0-8]  163.91 -37.24 0 bottom
Q12  CSD16301Q2  [WSON6_CSD13202Q2_80X80_0-8]  163.91 -34.34 0 bottom
Q13  CSD16301Q2  [WSON6_CSD13202Q2_80X80_0-8]  163.91 -40.46 0 bottom
Q14  CSD16301Q2  [WSON6_CSD13202Q2_80X80_0-8]  159.77 -46.69 0 bottom
Q15  CSD16301Q2  [WSON6_CSD13202Q2_80X80_0-8]  159.77 -43.79 0 bottom
Q16  CSD25310Q2  [SON6_CSD17313Q2_80X80]  65.2 -64.97 270 bottom
R1  1K  [RES0402_0-5]  19.23 -14.12 270 top
R2  0E  [RES0402_0-5]  33.15 -14.59 180 top
R3  10K  [RES0402_0-5]  33.15 -16.09 0 top
R4  10K  [RES0402_0-5]  26.75 -16.1 180 top
R5  10K  [RES0402_0-5]  72.16 -16.97 90 top
R6  12.7K_1%  [RES0402_0-5]  21.34 -17.09 270 top
R8  0E  [RES0402_0-5]  26.75 -17.55 0 top
R9  10K  [RES0402_0-5]  12.57 -18.06 0 top
R10  10K  [RES0402_0-5]  83.39 -18.56 90 top
R11  10K  [RES0402_0-5]  12.57 -19.81 0 top
R12  2.49K_1%  [RES0402_0-5]  136.94 -20.68 270 top
R13  0E  [RES0402_0-5]  138.79 -20.7 270 top
R15  10K  [RES0402_0-5]  12.7 -21.41 180 top
R16  10K  [RES0402_0-5]  12.68 -22.86 180 top
R17  1K  [RES0402_0-5]  25.89 -22.86 0 top
R19  10K  [RES0402_0-5]  89.49 -23.77 270 top
R20  0E  [RES0402_0-5]  90.94 -23.77 270 top
R21  10K  [RES0402_0-5]  92.41 -23.77 270 top
R22  11K_1%  [RES0402_0-5]  145.21 -23.84 0 top
R23  0E  [RES0402_0-5]  94.21 -46.33 0 top
R24  10K  [RES0402_0-5]  35.54 -24.13 180 top
R25  0E  [RES0402_0-5]  127.28 -24.31 0 top
R26  0E  [RES0402_0-5]  116.44 -24.32 0 top
R27  10K  [RES0402_0-5]  12.68 -24.36 180 top
R28  1K  [RES0402_0-5]  25.89 -24.36 0 top
R29  1K  [RES0402_0-5]  63.75 -23.77 0 top
R30  0E  [RES0402_0-5]  65.77 -24.64 90 top
R31  0E  [RES0402_0-5]  57.56 -23.65 0 top
R32  10K  [RES0402_0-5]  116.44 -25.84 180 top
R33  10K  [RES0402_0-5]  12.68 -25.86 180 top
R34  1K  [RES0402_0-5]  25.89 -25.86 0 top
R35  0E  [RES0406_0-5]  48.87 -25.91 180 top
R36  10K  [RES0402_0-5]  69.52 -26.21 180 top
R37  10K  [RES0402_0-5]  84.02 -26.52 0 top
R39  49.9K_1%  [RES0402_0-5]  87.13 -26.97 90 top
R40  10K  [RES0402_0-5]  88.52 -26.97 90 top
R41  10K  [RES0402_0-5]  90.68 -26.97 90 top
R42  1K  [RES0402_0-5]  92.82 -26.97 90 top
R43  10K  [RES0402_0-5]  94.29 -26.97 90 top
R44  10K  [RES0402_0-5]  95.81 -26.97 90 top
R45  10K  [RES0402_0-5]  97.34 -26.97 90 top
R46  0E  [RES0402_0-5]  116.44 -27.3 180 top
R47  10K  [RES0402_0-5]  12.68 -27.36 180 top
R48  1K  [RES0402_0-5]  25.89 -27.36 0 top
R49  0E  [RES0402_0-5]  112.47 -27.69 180 top
R50  0E  [RES0402_0-5]  127.36 -27.94 0 top
R51  0E  [RES0402_0-5]  133.46 -28.05 0 top
R52  10K  [RES0402_0-5]  12.68 -28.85 180 top
R53  1K  [RES0402_0-5]  25.89 -28.85 0 top
R54  100K_1%  [RES0402_0-5]  69.22 -28.91 180 top
R55  1K  [RES0402_0-5]  87.13 -29.34 90 top
R56  1K  [RES0402_0-5]  88.52 -29.34 90 top
R57  1K  [RES0402_0-5]  89.9 -29.34 90 top
R58  1K  [RES0402_0-5]  91.37 -29.34 90 top
R59  1K  [RES0402_0-5]  92.84 -29.34 90 top
R60  1K  [RES0402_0-5]  94.29 -29.34 90 top
R61  1K  [RES0402_0-5]  95.81 -29.34 90 top
R62  1K  [RES0402_0-5]  97.34 -29.34 90 top
R63  0E  [RES0402_0-5]  84.3 -33.05 90 top
R64  2.49K_1%  [RES0402_0-5]  133.48 -29.51 180 top
R65  0E  [RES0402_0-5]  83.21 -29.84 270 top
R66  10K  [RES0402_0-5]  12.68 -30.35 180 top
R67  1K  [RES0402_0-5]  25.89 -30.35 0 top
R68  2.49K_1%  [RES0402_0-5]  133.48 -30.94 0 top
R69  10K  [RES0402_0-5]  12.68 -31.85 180 top
R70  1K  [RES0402_0-5]  25.89 -31.85 0 top
R71  2.49K_1%  [RES0402_0-5]  133.2 -32.72 270 top
R72  2.49K_1%  [RES0402_0-5]  134.73 -32.72 270 top
R73  2.49K_1%  [RES0402_0-5]  136.22 -32.72 90 top
R74  2.49K_1%  [RES0402_0-5]  141.79 -32.72 270 top
R75  2.49K_1%  [RES0402_0-5]  143.29 -32.72 270 top
R76  2.49K_1%  [RES0402_0-5]  145.01 -32.72 270 top
R77  100K_1%  [RES0402_0-5]  44.39 -33.53 0 top
R78  0E  [RES0402_0-5]  73.72 -33.73 270 top
R79  220E  [RES0402_0-5]  5.06 -33.91 180 top
R80  453K_1%  [RES0402_0-5]  44.39 -34.92 180 top
R81  10K  [RES0402_0-5]  120.27 -35.33 0 top
R82  2.2K  [RES0402_0-5]  68.35 -36.17 0 top
R83  10K  [RES0402_0-5]  98.63 -35.41 270 top
R84  0E  [RES0402_0-5]  40.75 -35.64 90 top
R85  10K  [RES0402_0-5]  42.27 -35.64 270 top
R86  620E_1%  [RES0402_0-5]  5.06 -35.94 180 top
R87  10K  [RES0402_0-5]  72.12 -36.32 0 top
R88  2.2K  [RES0402_0-5]  68.35 -37.57 0 top
R89  10K  [RES0402_0-5]  64.88 -37.08 90 top
R90  10K  [RES0402_0-5]  49.07 -37.95 270 top
R91  220E  [RES0402_0-5]  5.06 -37.97 180 top
R92  10K  [RES0402_0-5]  11.18 -38.35 0 top
R93  62E_1%  [RES0402_0-5]  69.45 -39.14 0 top
R94  620E_1%  [RES0402_0-5]  19.43 -39.39 270 top
R95  2.49K_1%  [RES0402_0-5]  138.18 -39.85 270 top
R96  0E  [RES0406_0-5]  54.59 -41.15 180 top
R97  62E_1%  [RES0402_0-5]  69.45 -42.04 0 top
R98  1K  [RES0402_0-5]  20.5 -42.8 90 top
R99  1K  [RES0402_0-5]  22.05 -42.8 90 top
R100  1K  [RES0402_0-5]  23.52 -42.8 90 top
R101  1K  [RES0402_0-5]  24.99 -42.8 90 top
R102  11K_1%  [RES0402_0-5]  145.21 -42.89 0 top
R104  0E  [RES0402_0-5]  9.45 -43.23 270 top
R105  10K  [RES0402_0-5]  10.9 -43.23 90 top
R106  10K  [RES0402_0-5]  12.34 -43.23 90 top
R107  0E  [RES0402_0-5]  13.79 -43.23 270 top
R108  10K  [RES0402_0-5]  28.37 -44.32 90 top
R109  10K  [RES0402_0-5]  29.84 -44.32 90 top
R110  200K  [RES0402_0-5]  14.63 -44.96 0 top
R111  220E  [RES0402_0-5]  5.33 -45.31 0 top
R112  10K  [RES0402_0-5]  44.17 -45.32 90 top
R113  909K_1%  [RES0402_0-5]  14.63 -46.51 0 top
R114  220E  [RES0402_0-5]  5.33 -47.09 0 top
R115  0E  [RES0402_0-5]  133.46 -47.1 0 top
R116  10K  [RES0402_0-5]  39.27 -47.4 270 top
R117  3.48K_1%  [RES0402_0-5]  35.46 -47.88 0 top
R118  16.5K_1%  [RES0402_0-5]  37.62 -47.88 0 top
R119  4.7K  [RES0402_0-5]  14.63 -47.96 180 top
R120  4.7K  [RES0402_0-5]  72.22 -48.01 0 top
R121  10K  [RES0402_0-5]  64.34 -48.36 90 top
R122  10K  [RES0402_0-5]  65.61 -48.36 90 top
R123  2.49K_1%  [RES0402_0-5]  133.48 -48.55 180 top
R124  100K_1%  [RES0402_0-5]  50.11 -48.77 0 top
R125  10K  [RES0402_0-5]  46.53 -49.17 180 top
R126  10K  [RES0402_0-5]  72.22 -49.28 0 top
R127  0E  [RES0402_0-5]  48.21 -49.66 90 top
R128  10K  [RES0402_0-5]  150.47 -49.9 0 top
R129  2.49K_1%  [RES0402_0-5]  133.48 -49.99 0 top
R130  41.2K_1%  [RES0402_0-5]  50.11 -50.16 180 top
R131  0E  [RES0402_0-5]  160.38 -51.16 0 top
R132  2.49K_1%  [RES0402_0-5]  133.2 -51.77 270 top
R133  2.49K_1%  [RES0402_0-5]  134.73 -51.77 270 top
R134  2.49K_1%  [RES0402_0-5]  136.22 -51.77 90 top
R135  2.2K  [RES0402_0-5]  140.19 -51.77 90 top
R136  2.2K  [RES0402_0-5]  141.66 -51.77 90 top
R137  2.49K_1%  [RES0402_0-5]  143.29 -51.77 270 top
R138  2.49K_1%  [RES0402_0-5]  144.76 -51.77 270 top
R139  2.49K_1%  [RES0402_0-5]  146.59 -51.77 270 top
R140  0E  [RES0402_0-5]  150.47 -51.79 180 top
R141  0E  [RES0402_0-5]  145.06 -54.1 180 top
R142  3.48K_1%  [RES0402_0-5]  42.24 -54.38 270 top
R143  2.94K_1%  [RES0402_0-5]  43.61 -54.38 90 top
R144  2.94K_1%  [RES0402_0-5]  44.98 -54.38 90 top
R145  3.48K_1%  [RES0402_0-5]  46.35 -54.38 270 top
R146  2.94K_1%  [RES0402_0-5]  47.73 -54.38 90 top
R147  3.48K_1%  [RES0402_0-5]  49.1 -54.38 270 top
R148  2.94K_1%  [RES0402_0-5]  50.47 -54.38 90 top
R149  3.48K_1%  [RES0402_0-5]  51.84 -54.38 270 top
R150  2.94K_1%  [RES0402_0-5]  53.21 -54.38 90 top
R151  3.48K_1%  [RES0402_0-5]  54.58 -54.38 270 top
R152  2.94K_1%  [RES0402_0-5]  55.96 -54.38 90 top
R153  3.48K_1%  [RES0402_0-5]  57.33 -54.38 270 top
R154  2.94K_1%  [RES0402_0-5]  58.7 -54.38 90 top
R155  3.48K_1%  [RES0402_0-5]  60.07 -54.38 270 top
R156  2.94K_1%  [RES0402_0-5]  61.44 -54.38 90 top
R157  3.48K_1%  [RES0402_0-5]  62.81 -54.38 270 top
R158  0E  [RES0402_0-5]  145.01 -55.6 180 top
R159  0E  [RES0603_0-75]  9.27 -57.28 90 top
R160  0E  [RES0603_0-75]  25.51 -57.28 90 top
R161  0E  [RES0402_0-5]  100.99 -58.67 180 top
R162  22E_1%  [RES0201_0-5]  70.31 -59.33 90 top
R163  0E  [RES0402_0-5]  100.99 -61.21 0 top
R164  1K  [RES0402_0-5]  65.43 -65 270 top
R165  10K  [RES0402_0-5]  168.76 -11.79 270 bottom
R166  220E  [RES0402_0-5]  165.76 -11.79 90 bottom
R167  220E  [RES0402_0-5]  167.34 -11.79 90 bottom
R168  220E  [RES0402_0-5]  174.97 -11.4 270 bottom
R169  110E  [RES0402_0-5]  173.63 -11.4 270 bottom
R170  1K  [RES0402_0-5]  27.61 -14.12 270 bottom
R171  1K  [RES0402_0-5]  9.28 -14.12 270 bottom
R172  10K  [RES0402_0-5]  166.77 -15.34 90 bottom
R173  10K  [RES0402_0-5]  171.47 -15.34 90 bottom
R174  10K  [RES0402_0-5]  172.93 -16.61 270 bottom
R175  88.7K_1%  [RES0402_0-5]  21.79 -16.51 180 bottom
R176  100K_1%  [RES0402_0-5]  21.79 -17.96 0 bottom
R177  10K  [RES0402_0-5]  21.77 -19.42 0 bottom
R178  2.2K  [RES0402_0-5]  9.17 -19.68 180 bottom
R179  0E  [RES0402_0-5]  77.96 -20.57 270 bottom
R180  0E  [RES0402_0-5]  76.56 -20.57 270 bottom
R181  10K  [RES0402_0-5]  75.16 -20.57 90 bottom
R182  2.2K  [RES0402_0-5]  11.58 -20.62 180 bottom
R183  10K  [RES0402_0-5]  81.2 -20.65 180 bottom
R184  2.49K_1%  [RES0402_0-5]  136.94 -20.68 90 bottom
R185  0E  [RES0402_0-5]  138.79 -20.7 270 bottom
R186  2.2K  [RES0402_0-5]  9.17 -21.56 180 bottom
R187  2.2K  [RES0402_0-5]  11.58 -22.5 180 bottom
R188  10K  [RES0402_0-5]  21.89 -22.63 180 bottom
R189  10K  [RES0402_0-5]  9.17 -23.44 0 bottom
R190  10K  [RES0402_0-5]  105.69 -24.03 90 bottom
R191  10K  [RES0402_0-5]  24.94 -24.03 270 bottom
R192  10K  [RES0402_0-5]  92.1 -24.21 90 bottom
R193  10K  [RES0402_0-5]  90.1 -24.21 90 bottom
R194  10K  [RES0402_0-5]  88.65 -24.21 90 bottom
R195  14.7K_1%  [RES0402_0-5]  21.79 -25.68 0 bottom
R196  10K  [RES0402_0-5]  11.58 -24.38 0 bottom
R197  10K  [RES0402_0-5]  9.17 -25.32 0 bottom
R198  16.9K_1%  [RES0402_0-5]  19.94 -25.4 90 bottom
R199  5.23K_1%  [RES0402_0-5]  18.21 -25.4 270 bottom
R200  1M  [RES0603_0-75]  172.67 -37.73 270 bottom
R201  100K_1%  [RES0402_0-5]  21.79 -24.23 0 bottom
R202  10K  [RES0402_0-5]  11.58 -26.26 0 bottom
R203  10K  [RES0402_0-5]  97.41 -27 270 bottom
R204  10K  [RES0402_0-5]  95.86 -27 270 bottom
R205  49.9K_1%  [RES0402_0-5]  94.31 -27 270 bottom
R206  49.9K_1%  [RES0402_0-5]  90.68 -27 270 bottom
R207  10K  [RES0402_0-5]  88.52 -27 270 bottom
R208  10K  [RES0402_0-5]  87.13 -27 270 bottom
R209  10K  [RES0402_0-5]  9.17 -27.2 0 bottom
R210  220E  [RES0402_0-5]  180.26 -18.42 0 bottom
R211  10K  [RES0402_0-5]  11.58 -28.14 0 bottom
R212  10K  [RES0402_0-5]  16.82 -28.27 180 bottom
R213  0E  [RES0402_0-5]  95.81 -29.34 90 bottom
R214  1K  [RES0402_0-5]  94.29 -29.34 90 bottom
R215  1K  [RES0402_0-5]  91.37 -29.34 90 bottom
R216  1K  [RES0402_0-5]  88.57 -29.34 90 bottom
R217  1K  [RES0402_0-5]  87.12 -29.36 90 bottom
R218  2.49K_1%  [RES0402_0-5]  133.48 -29.51 0 bottom
R219  15K  [RES0402_0-5]  16.82 -29.69 0 bottom
R220  220E  [RES0402_0-5]  161.34 -37.39 90 bottom
R221  2.49K_1%  [RES0402_0-5]  133.48 -30.94 180 bottom
R222  100E_1%  [RES0402_0-5]  16.82 -31.27 180 bottom
R223  220E  [RES0402_0-5]  161.34 -34.49 90 bottom
R224  10K  [RES0402_0-5]  42.55 -32.13 270 bottom
R225  2.49K_1%  [RES0402_0-5]  145.09 -32.72 90 bottom
R226  2.49K_1%  [RES0402_0-5]  143.29 -32.72 90 bottom
R227  2.49K_1%  [RES0402_0-5]  141.81 -32.72 90 bottom
R228  2.49K_1%  [RES0402_0-5]  136.22 -32.79 270 bottom
R229  2.49K_1%  [RES0402_0-5]  134.73 -32.79 90 bottom
R230  2.49K_1%  [RES0402_0-5]  133.2 -32.79 90 bottom
R231  0E  [RES0402_0-5]  16.82 -33.73 180 bottom
R232  1.69K_1%  [RES0402_0-5]  127.99 -33.8 270 bottom
R233  3.57K_1%  [RES0402_0-5]  126.47 -33.8 90 bottom
R234  10K  [RES0402_0-5]  71.63 -34.62 180 bottom
R235  2.2K  [RES0402_0-5]  38.9 -35.31 270 bottom
R236  10K  [RES0402_0-5]  142.07 -36.27 90 bottom
R237  4.7K  [RES0402_0-5]  67.23 -37.16 270 bottom
R238  4.7K  [RES0402_0-5]  65.91 -37.16 270 bottom
R239  499E_1%  [RES0201_0-5]  86.97 -38.33 90 bottom
R240  0E  [RES0402_0-5]  72.24 -39.45 180 bottom
R241  10K  [RES0402_0-5]  149.4 -39.6 0 bottom
R242  2.49K_1%  [RES0402_0-5]  138.18 -39.85 90 bottom
R243  10K  [RES0402_0-5]  160.66 -40.46 90 bottom
R244  0E  [RES0402_0-5]  72.21 -40.94 180 bottom
R245  10K  [RES0402_0-5]  149.4 -41.12 0 bottom
R246  10K  [RES0402_0-5]  16.31 -41.25 0 bottom
R247  4.99K_1%  [RES0402_0-5]  127.99 -44.52 270 bottom
R248  1.87K_1%  [RES0402_0-5]  126.47 -44.52 90 bottom
R249  51E  [RES0402_0-5]  15.35 -45.17 90 bottom
R250  10K  [RES0402_0-5]  112.52 -45.97 180 bottom
R251  0E  [RES0402_0-5]  2.52 -46.48 90 bottom
R252  220E  [RES0402_0-5]  157 -47.22 90 bottom
R253  1M  [RES0603_0-75]  174.62 -60.24 270 bottom
R254  2.49K_1%  [RES0402_0-5]  133.48 -48.56 0 bottom
R255  11K_1%  [RES0402_0-5]  65.07 -48.79 0 bottom
R256  4.87K_1%  [RES0402_0-5]  23.39 -49.11 0 bottom
R257  220E  [RES0402_0-5]  157 -43.94 90 bottom
R258  220E  [RES0402_0-5]  180.27 -39.07 0 bottom
R259  0E  [RES0402_0-5]  160.38 -53.52 0 bottom
R260  2.49K_1%  [RES0402_0-5]  133.48 -49.99 180 bottom
R261  0E  [RES0402_0-5]  86.23 -51.41 180 bottom
R262  100K_1%  [RES0402_0-5]  65.07 -50.62 180 bottom
R263  0E  [RES0402_0-5]  160.38 -51.16 0 bottom
R264  2.49K_1%  [RES0402_0-5]  146.59 -51.77 90 bottom
R265  2.49K_1%  [RES0402_0-5]  144.76 -51.77 90 bottom
R266  2.49K_1%  [RES0402_0-5]  143.29 -51.77 90 bottom
R267  2.49K_1%  [RES0402_0-5]  136.22 -51.77 270 bottom
R268  2.49K_1%  [RES0402_0-5]  134.73 -51.77 90 bottom
R269  2.49K_1%  [RES0402_0-5]  133.2 -51.77 90 bottom
R270  0E  [RES0402_0-5]  164.68 -52.02 0 bottom
R271  22E_1%  [RES0201_0-5]  69.47 -54.74 0 bottom
R272  49.9K_1%  [RES0402_0-5]  156.51 -55.17 270 bottom
R273  49.9K_1%  [RES0402_0-5]  154.79 -55.17 270 bottom
R274  49.9K_1%  [RES0402_0-5]  152.98 -55.17 270 bottom
R275  10K  [RES0402_0-5]  142.62 -55.32 90 bottom
R276  10K  [RES0402_0-5]  161.62 -58.12 0 bottom
R277  59E_1%  [RES0402_0-5]  165.76 -59.21 180 bottom
R278  59E_1%  [RES0402_0-5]  163.86 -59.21 180 bottom
R279  49.9K_1%  [RES0402_0-5]  156.51 -61.52 270 bottom
R280  49.9K_1%  [RES0402_0-5]  154.79 -61.52 270 bottom
R281  49.9K_1%  [RES0402_0-5]  152.98 -61.52 270 bottom
R282  220E  [RES0402_0-5]  175.98 -65.04 270 bottom
R283  220E  [RES0402_0-5]  174.48 -65.04 270 bottom
R284  220E  [RES0402_0-5]  172.98 -65.04 270 bottom
R285  220E  [RES0402_0-5]  171.48 -65.04 270 bottom
R286  0E  [RES0402_0-5]  89.53 -47.8 0 bottom
R287  0E  [RES0402_0-5]  87.25 -43.64 0 bottom
R586  1K  [RES0402_0-5]  96.98 -35.03 90 top
R587  1K  [RES0402_0-5]  95.22 -34.65 90 top
R588  10K  [RES0402_0-5]  97.21 -32.44 90 top
R589  10K  [RES0402_0-5]  96.95 -32.28 270 bottom
R590  10K  [RES0402_0-5]  92.61 -34.72 270 top
R591  10K  [RES0402_0-5]  92.61 -34.72 90 bottom
R592  100K_1%  [RES0402_0-5]  32.93 -62.42 180 bottom
R593  1K  [RES0402_0-5]  34.16 -60.68 0 top
R594  0E  [RES0402_0-5]  103.26 -42.76 90 bottom
R595  0E  [RES0402_0-5]  103.78 -43.28 0 bottom
R596  0E  [RES0402_0-5]  99.95 -37.59 90 top
R597  0E  [RES0402_0-5]  100.47 -38.11 0 top
R598  10K  [RES0402_0-5]  123.77 -50.9 90 top
R599  220E  [RES0402_0-5]  123.06 -49.94 0 bottom
R600  10K  [RES0402_0-5]  123.04 -51.46 0 bottom
SW1  436331045822  [SW4_436331045822_190X190_SMD_1-7]  13.24 -11.15 180 top
SW2  436331045822  [SW4_436331045822_190X190_SMD_1-7]  21.92 -11.15 180 top
SW3  436331045822  [SW4_436331045822_190X190_SMD_1-7]  30.41 -11.15 180 top
SW4  416131160808  [SW16_416131160808_460X230_SMD_2-7]  19.28 -27.81 270 top
SW5  436331045822  [SW4_436331045822_190X190_SMD_1-7]  71.68 -65.4 0 top
SW6  TDA01H0SB1R  [SW_TDA01H0S_240X90_SMD_2-3]  119.86 -53.72 0 top
TP1  -  [TP20_SMD]  31.72 -19.02 270 top
TP2  THRU HOLE  [TP_40X65]  33.89 -19.81 0 top
TP3  THRU HOLE  [TP_40X65]  36.43 -19.81 0 top
TP4  -  [TP20_SMD]  142.73 -20.83 0 top
TP5  -  [TP40_SMD]  63.78 -21.87 180 top
TP6  -  [TP20_SMD]  7.24 -25.88 0 top
TP7  -  [TP40_SMD]  55.61 -25.53 0 top
TP9  THRU HOLE  [TP_40X65]  36.7 -29.49 0 top
TP11  -  [TP20_SMD]  138.79 -32.64 0 top
TP12  -  [TP20_SMD]  61.62 -33.86 0 top
TP13  -  [TP20_SMD]  71.17 -34.67 0 top
TP14  -  [TP20_SMD]  72.42 -34.67 0 top
TP15  -  [TP20_SMD]  20.42 -34.8 0 top
TP16  -  [TP20_SMD]  21.79 -34.8 0 top
TP17  -  [TP20_SMD]  23.16 -34.8 0 top
TP18  -  [TP20_SMD]  24.53 -34.8 0 top
TP19  -  [TP20_SMD]  61.62 -35.1 0 top
TP20  -  [TP40_SMD]  122.05 -35.33 270 top
TP21  -  [TP20_SMD]  71.56 -37.72 0 top
TP22  -  [TP20_SMD]  72.72 -37.72 0 top
TP23  -  [TP40_SMD]  56.54 -38.05 0 top
TP24  -  [TP20_SMD]  59.61 -38.48 0 top
TP25  -  [TP20_SMD]  142.73 -39.88 0 top
TP26  -  [TP20_SMD]  15.85 -41.33 0 top
TP27  -  [TP40_SMD]  2.03 -43.18 0 top
TP28  -  [TP20_SMD]  7.85 -43.71 180 top
TP29  -  [TP20_SMD]  16.26 -45.77 180 top
TP30  -  [TP40_SMD]  125.17 -46.2 270 top
TP31  -  [TP20_SMD]  74.27 -49.25 0 top
TP32  -  [TP40_SMD]  19.94 -49.05 0 top
TP33  -  [TP20_SMD]  138.79 -51.69 0 top
TP34  -  [TP20_SMD]  159.87 -52.55 0 top
TP35  -  [TP40_SMD]  36.45 -57.78 0 top
TP36  THRU HOLE  [TP_40X65]  29.31 -62.94 0 top
TP37  THRU HOLE  [TP_40X65]  163.58 -11.48 0 top
TP38  THRU HOLE  [TP_40X65]  87.48 -65.63 0 top
TP39  -  [TP40_SMD]  38.46 -52.2 0 top
TP40  -  [TP20_SMD]  35 -17.12 0 top
TP41  -  [TP20_SMD]  90.14 -47.47 0 top
TP42  -  [TP20_SMD]  70.59 -45.34 0 top
TP43  -  [TP20_SMD]  70.13 -35.51 0 top
TP44  -  [TP20_SMD]  73.66 -48.29 0 top
TP45  -  [TP20_SMD]  90.5 -38.56 0 top
TP46  -  [TP20_SMD]  72.69 -43.54 0 top
TP47  -  [TP20_SMD]  91.92 -40.61 0 top
TP48  -  [TP20_SMD]  80.54 -32.84 0 top
TP49  -  [TP20_SMD]  7.82 -33.12 0 top
TP50  -  [TP20_SMD]  164.82 -52.12 0 top
TP51  -  [TP20_SMD]  55.88 -34.62 0 top
TP52  -  [TP20_SMD]  84.51 -51.51 0 top
TP53  -  [TP40_SMD]  26.44 -50.27 0 top
U1  SN74LVC1G11DCKR  [SC70-6]  29.82 -16.74 0 top
U2  S25HL512TFAMHI010  [SOIC16_W_2-7]  76.69 -23.49 180 top
U3  25.000MHz  [OSC4_ASEK_130X100_SMD_1-2]  113.31 -24.92 0 top
U4  SN74AVC8T245RHL  [QFN24_19-68_220X140_1]  31.09 -25.27 270 top
U5  TPS7A2518DRVR  [SON6_25-59_85X85_0-8]  60.94 -25.78 180 top
U6  LMK1C1103PWR  [TSSOP8_25-59_125X180_1-2]  121.77 -26.16 0 top
U7  DP83869HMRGZT  [QFN48_19-68_280X280_1_EP4-2]  139.93 -26.59 180 top
U8  SN74CB3Q3125PWR  [TSSOP14_25-59_205X180_1-2]  104.67 -26.8 180 top
U9  TCA9617BDGKR  [VSSOP8_25-59_120X120_1-1]  7.35 -29.84 180 top
U10  TPS62822DLCT  [VSONHR8_TPS62823_60X80_1]  44.18 -31.24 90 top
U11  SN74LV1T34DCKR  [SC70-5_1-1]  76.32 -33.65 0 top
U12  SN74CB3Q3125PWR  [TSSOP14_25-59_205X180_1-2]  104.67 -33.65 180 top
U13  SN74LVC3G17DCUR  [VSSOP8_19-68_85X95_0-9]  59.51 -34.52 90 top
U14  TLV75518PDBVR  [SOT23-5_1-5]  52.6 -36.91 0 top
U15  SN74AHC1G02DRLR  [SOT553-5_0-6]  14.35 -39.12 0 top
U16  TXS0102DCUR  [VSSOP8_19-68_85X95_0-9]  29.18 -40.28 180 top
U17  AT24CM01  [TSSOP8_25-59_125X180_1-2]  64.37 -42.8 90 top
U18  XAM2434BSFGHIALX  [BGA293_19-68_440X440_1]  81.89 -43.81 90 top
U19  DP83869HMRGZT  [QFN48_19-68_280X280_1_EP4-2]  139.93 -45.64 180 top
U20  TUSB320LAIRWBR  [X2QFN12_TUSB322I_60X60_0-4]  11.72 -46.29 90 top
U21  TPS62822DLCT  [VSONHR8_TPS62823_60X80_1]  49.89 -46.48 90 top
U22  TMUX154EDGSR  [MSOP10_19-68_120X120_1-1]  155.55 -50.9 0 top
U23  TPS22965DSGT  [WSON8_19-68_80X80_0-8]  30.94 -51.74 0 top
U24  TPD4E02B04DQAR  [USON10_TPD4E05U_40X100_0-6]  8.62 -52.52 0 top
U25  SN74AVC4T245PW  [TSSOP16_25-59_205X180]  70.36 -54.48 90 top
U26  TCA6408ARGTR  [QFN16_19-68_120X120_1_EP1-6]  25.82 -20.17 270 bottom
U27  TPS386000RGPR  [QFN20_19-68_160X160_1]  16.74 -20.6 270 bottom
U28  SN74LVC1G08DBVRE4  [SOT23-5]  36.81 -23.24 180 bottom
U30  TMUX154EDGSR  [MSOP10_19-68_120X120_1-1]  101.02 -24.13 180 bottom
U31  SN74LVC1G08DBVRE4  [SOT23-5]  76.69 -24.13 270 bottom
U32  TXB0106PWR  [TSSOP16_25-59_205X180]  121.79 -25.83 0 bottom
U33  TPS74801DRCR  [VSON10_TPS74801-Q1_120X120_1]  123.55 -33.17 0 bottom
U34  SN74LVC1G08DBVRE4  [SOT23-5]  139.4 -35.51 90 bottom
U35  TPIC2810D  [SOIC16_1-8]  155.17 -36.58 180 bottom
U36  LM4040B25IDCKR  [SC70-5_1-1]  41.4 -36.19 0 bottom
U37  TM4C1294NCPDTT3R  [TQFP128_15-74_550X550_1-2]  26.9 -38.99 180 bottom
U38  TPS74633PQWDRVRQ1  [SON6_25-59_85X85_0-8]  13.06 -42.67 180 bottom
U39  TPS74801DRCR  [VSON10_TPS74801-Q1_120X120_1]  123.55 -43.89 0 bottom
U40  TS3DDR3812RUAR  [TQFN42_19-68_140X360_0-8]  108 -45.34 180 bottom
U41  TPS7A0533PDBVT  [SOT23-5_1-5#2]  6.84 -46.1 0 bottom
U42  SN74AVC2T244DQMR  [X2SON8_15-74_70X50]  67.08 -54.31 180 bottom
U43  SN74LVC1G08DBVRE4  [SOT23-5]  139.95 -55.07 90 bottom
U44  TCAN1044VDRBRQ1  [SON8_25-59_130X130_1]  164.85 -55.91 270 bottom
U45  SN74AVC4T245PW  [TSSOP16_25-59_205X180]  33.96 -57.33 90 bottom
U46  TXB0106RGYR  [QFN16_19-68_160X140_1]  142.98 -60.96 90 bottom
U50  TMUX1574RSVR  [UQFN16_TMUX1574_70X100_0-6]  92.02 -59.84 270 bottom
U51  TMUX1574RSVR  [UQFN16_TMUX1574_70X100_0-6]  114.88 -22.99 270 bottom
U52  TMUX1574RSVR  [UQFN16_TMUX1574_70X100_0-6]  118.69 -52.07 0 bottom
Y1  16.000MHz  [XTAL4_LFXTAL055474_130X110_SMD_0-8]  12.3 -35.69 270 bottom

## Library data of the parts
C1-C82 C84-C86 C88 C90-C114 C116-C126 C128-C163 C165-C194 C196-C260 C262 C263 C265-C273 = CAP
D1 D2 D4-D8 = DIODE_TVS_DUAL
D3 = DIODE_ZENER_SOT23_13
FB1-FB9 = INDUCTOR_FERRITE
FL1 = EMIFILTER_IND
J1 J2 J5 J6 = RECP_10X2
J9 J11 J14 = HEADER_3X1
J10 = CON_USB-C_24_6327233
J12 J21 = HEADER_5X1
J13 J17 = HEADER_6X1
J15 = CON_FLEX_40X1_20347
J16 = HEADER_5X2
J18 J19 = CON_RJ45-14_LPJG16314A4NL
J20 = CON_USB_MINI-B
J22 = HEADER_2X1
L1 L2 = INDUCTOR
L3 = INDUCTOR_DLW31S
LD1 LD2 LD6-LD15 LD17 = DIODE_LED
LD3 = LED4_150066RV54050
Q3-Q6 Q9-Q15 = MOSFET_CSD17313Q2
Q7 Q8 Q16 = MOSFET_CSD25310Q2
R1-R6 R8-R13 R15-R17 R19 R21 R22 R24-R37 R39-R50 R52-R62 R64-R102 R104-R114 R116-R285 R586-R594 R596 R598-R600 = RESISTOR
R20 R23 R51 R63 R115 R286 R287 R595 R597 = RESISTOR: signal model: RESISTOR_RES0402_0-5_0E_0E
SW1-SW3 SW5 = SW4_EVQP
SW4 = SW16_CHS-08A
SW6 = SW2_CHS-01TA
TP1-TP7 TP9 TP11-TP53 = TESTPOINT
U1 = SN74LVC1G11DCKR_SC70-6
U2 = S25HL512TFAMHI01_SOIC16
U3 = OSC4_EQXP-HC33
U4 = SN74AVC8T245RHL_QFN24
U5 = TPS7A2518_WSON6
U6 = LMK1C1103_TSSOP8
U7 U19 = DP83869HM_VQFN48
U8 U12 = SN74CBTLV3125PWR_TSSOP14
U9 = TCA9617BDGKR_VSSOP8
U10 U21 = TPS62823_VSONHR8
U11 = SN74LVC1G07DBVR_SOT23-5
U13 = SN74LVC3G17DCUR_VSSOP8
U14 U41 = TLV71318PDBVT_SOT23-5
U15 = SN74AHC1G02DBV_SOT23-5
U16 = TXS0102DCUR_VSSOP8
U17 = AT24HC04B-TH-B_TSSOP8
U18 = AM243X SOC_LP_EVM_BGA293
U20 = TUSB320LAI_X2QFN12
U22 U30 = TMUX154EDGSR_VSSOP10
U23 = TPS22965DSGT_WSON8
U24 = TPD4E02B04DQAR_USON10
U25 U45 = SN74AVC4T245PW_TSSOP16
U26 = TCA6408ARGTR_VQFN16
U27 = TPS386000RGPR_QFN20
U28 U31 U34 U43 = SN74LVC1G08DBVRE4_SOT23-5
U32 = TXB0106PWR_TSSOP16
U33 U39 = TPS74801DRCR_SON10
U35 = TPIC2810D_SOIC16
U36 = LM4040B25IDCKR_SC70-5
U37 = TM4C1294NCPDTT3R_TQFP128
U38 = TPS74618_WSON6
U40 = TS3DDR3812RUAR_WQFN42
U42 = SN74AVC2T244DQMR_X2SON8
U44 = TCAN1044V-Q1_SON8
U46 = TXB0106RGYR_VQFN16
U50-U52 = TMUX1574_UQFN16
Y1 = CRY4_13

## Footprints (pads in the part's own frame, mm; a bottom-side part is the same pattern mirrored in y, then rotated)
BGA293_19-68_440X440_1
  round 0.254 smd: A1(-5,5) A2(-4.5,5) A3(-4,5) A5(-3,5) A6(-2.5,5) A8(-1.5,5) A9(-1,5) A11(0,5) A12(0.5,5) A14(1.5,5) A15(2,5) A17(3,5) A18(3.5,5) A20(4.5,5) A21(5,5) AA1(-5,-5) AA2(-4.5,-5) AA4(-3.5,-5) AA5(-3,-5) AA7(-2,-5) AA8(-1.5,-5) AA10(-0.5,-5) AA11(0,-5) AA13(1,-5) AA14(1.5,-5) AA16(2.5,-5) AA17(3,-5) AA19(4,-5) AA20(4.5,-5) AA21(5,-5) B1(-5,4.5) B2(-4.5,4.5) B3(-4,4.5) B4(-3.5,4.5) B5(-3,4.5) B6(-2.5,4.5) B7(-2,4.5) B8(-1.5,4.5) B9(-1,4.5) B10(-0.5,4.5) B11(0,4.5) B12(0.5,4.5) B13(1,4.5) B14(1.5,4.5) B15(2,4.5) B16(2.5,4.5) B17(3,4.5) B18(3.5,4.5) B19(4,4.5) B20(4.5,4.5) B21(5,4.5) C2(-4.5,4) C5(-3,4) C6(-2.5,4) C9(-1,4) C11(0,4) C13(1,4) C16(2.5,4) C17(3,4) C20(4.5,4) C21(5,4) D1(-5,3.5) D2(-4.5,3.5) D4(-3.5,3.5) D6(-2.5,3.5) D9(-1,3.5) D10(-0.5,3.5) D12(0.5,3.5) D13(1,3.5) D16(2.5,3.5) D17(3,3.5) D18(3.5,3.5) D20(4.5,3.5) E1(-5,3) E2(-4.5,3) E3(-4,3) E4(-3.5,3) E6(-2.5,3) E7(-2,3) E8(-1.5,3) E9(-1,3) E11(0,3) E13(1,3) E14(1.5,3) E15(2,3) E16(2.5,3) E19(4,3) E20(4.5,3) E21(5,3) F2(-4.5,2.5) F3(-4,2.5) F4(-3.5,2.5) F5(-3,2.5) F8(-1.5,2.5) F11(0,2.5) F14(1.5,2.5) F17(3,2.5) F18(3.5,2.5) F19(4,2.5) F20(4.5,2.5) F21(5,2.5) G1(-5,2) G2(-4.5,2) G5(-3,2) G6(-2.5,2) G9(-1,2) G10(-0.5,2) G11(0,2) G12(0.5,2) G13(1,2) G16(2.5,2) G17(3,2) G20(4.5,2) H1(-5,1.5) H2(-4.5,1.5) H5(-3,1.5) H6(-2.5,1.5) H7(-2,1.5) H8(-1.5,1.5) H11(0,1.5) H14(1.5,1.5) H15(2,1.5) H16(2.5,1.5) H17(3,1.5) H20(4.5,1.5) H21(5,1.5) J2(-4.5,1) J3(-4,1) J4(-3.5,1) J5(-3,1) J6(-2.5,1) J9(-1,1) J10(-0.5,1) J11(0,1) J12(0.5,1) J13(1,1) J16(2.5,1) J17(3,1) J18(3.5,1) J19(4,1) J20(4.5,1) J21(5,1) K1(-5,0.5) K2(-4.5,0.5) K4(-3.5,0.5) K6(-2.5,0.5) K7(-2,0.5) K8(-1.5,0.5) K11(0,0.5) K14(1.5,0.5) K15(2,0.5) K16(2.5,0.5) K18(3.5,0.5) K20(4.5,0.5) L1(-5,0) L2(-4.5,0) L3(-4,0) L5(-3,0) L6(-2.5,0) L9(-1,0) L10(-0.5,0) L11(0,0) L12(0.5,0) L13(1,0) L16(2.5,0) L17(3,0) L19(4,0) L20(4.5,0) L21(5,0) M2(-4.5,-0.5) M4(-3.5,-0.5) M6(-2.5,-0.5) M7(-2,-0.5) M8(-1.5,-0.5) M11(0,-0.5) M14(1.5,-0.5) M15(2,-0.5) M16(2.5,-0.5) M18(3.5,-0.5) M20(4.5,-0.5) M21(5,-0.5) N1(-5,-1) N2(-4.5,-1) N3(-4,-1) N4(-3.5,-1) N5(-3,-1) N6(-2.5,-1) N9(-1,-1) N10(-0.5,-1) N11(0,-1) N12(0.5,-1) N13(1,-1) N16(2.5,-1) N17(3,-1) N18(3.5,-1) N19(4,-1) N20(4.5,-1) P1(-5,-1.5) P2(-4.5,-1.5) P5(-3,-1.5) P6(-2.5,-1.5) P7(-2,-1.5) P8(-1.5,-1.5) P11(0,-1.5) P14(1.5,-1.5) P15(2,-1.5) P16(2.5,-1.5) P17(3,-1.5) P20(4.5,-1.5) P21(5,-1.5) R2(-4.5,-2) R5(-3,-2) R6(-2.5,-2) R9(-1,-2) R10(-0.5,-2) R11(0,-2) R12(0.5,-2) R13(1,-2) R16(2.5,-2) R17(3,-2) R20(4.5,-2) R21(5,-2) T1(-5,-2.5) T2(-4.5,-2.5) T3(-4,-2.5) T4(-3.5,-2.5) T5(-3,-2.5) T8(-1.5,-2.5) T11(0,-2.5) T14(1.5,-2.5) T17(3,-2.5) T18(3.5,-2.5) T19(4,-2.5) T20(4.5,-2.5) U1(-5,-3) U2(-4.5,-3) U3(-4,-3) U6(-2.5,-3) U7(-2,-3) U8(-1.5,-3) U9(-1,-3) U11(0,-3) U13(1,-3) U14(1.5,-3) U15(2,-3) U16(2.5,-3) U18(3.5,-3) U19(4,-3) U20(4.5,-3) U21(5,-3) V2(-4.5,-3.5) V4(-3.5,-3.5) V5(-3,-3.5) V6(-2.5,-3.5) V9(-1,-3.5) V10(-0.5,-3.5) V12(0.5,-3.5) V13(1,-3.5) V16(2.5,-3.5) V18(3.5,-3.5) V20(4.5,-3.5) V21(5,-3.5) W1(-5,-4) W2(-4.5,-4) W5(-3,-4) W6(-2.5,-4) W9(-1,-4) W11(0,-4) W13(1,-4) W16(2.5,-4) W17(3,-4) W20(4.5,-4) Y1(-5,-4.5) Y2(-4.5,-4.5) Y3(-4,-4.5) Y4(-3.5,-4.5) Y5(-3,-4.5) Y6(-2.5,-4.5) Y7(-2,-4.5) Y8(-1.5,-4.5) Y9(-1,-4.5) Y10(-0.5,-4.5) Y11(0,-4.5) Y12(0.5,-4.5) Y13(1,-4.5) Y14(1.5,-4.5) Y15(2,-4.5) Y16(2.5,-4.5) Y17(3,-4.5) Y18(3.5,-4.5) Y19(4,-4.5) Y20(4.5,-4.5) Y21(5,-4.5)
CAP0201_0-5
  rect 0.356x0.33 smd: 1(-0.28,0) 2(0.28,0)
CAP0402_0-75
  rect 0.559x0.635 smd: 1(-0.49,0) 2(0.49,0)
CAP0603_1
  rect 0.711x0.889 smd: 1(-0.7,0) 2(0.7,0)
CAP1206_2
  rect 0.991x1.702 smd: 1(-1.35,0) 2(1.35,0)
CAP1210_1-5
  rect 0.965x2.718 smd: 1(-1.65,0) 2(1.65,0)
CON_FLEX1X40_687140183622_S_R_S_1-3
  rect 0.305x1.041 smd: 1(-9.75,2.405) 2(-9.25,2.405) 3(-8.75,2.405) 4(-8.25,2.405) 5(-7.75,2.405) 6(-7.25,2.405) 7(-6.75,2.405) 8(-6.25,2.405) 9(-5.75,2.405) 10(-5.25,2.405) 11(-4.75,2.405) 12(-4.25,2.405) 13(-3.75,2.405) 14(-3.25,2.405) 15(-2.75,2.405) 16(-2.25,2.405) 17(-1.75,2.405) 18(-1.25,2.405) 19(-0.75,2.405) 20(-0.25,2.405) 21(0.25,2.405) 22(0.75,2.405) 23(1.25,2.405) 24(1.75,2.405) 25(2.25,2.405) 26(2.75,2.405) 27(3.25,2.405) 28(3.75,2.405) 29(4.25,2.405) 30(4.75,2.405) 31(5.25,2.405) 32(5.75,2.405) 33(6.25,2.405) 34(6.75,2.405) 35(7.25,2.405) 36(7.75,2.405) 37(8.25,2.405) 38(8.75,2.405) 39(9.25,2.405) 40(9.75,2.405)
  rect 1.753x1.397 smd: 41(-12.025,0.505) 42(12.025,0.505)
CON_MUSBB5_629105150521_S_R_S_2-7
  round 0.686 hole 0.813 unplated: (-2.5,1.848) (2.5,1.848)
  rect 0.457x1.295 smd: 1(-1.3,2.948) 2(-0.65,2.948) 3(0,2.948) 4(0.65,2.948) 5(1.3,2.948)
  oval 1.448x2.311 hole 0.864x1.727: 6(-3.725,2.898) 7(3.725,2.898)
  oval 1.143x1.803 hole 0.559x1.219: 8(-3.875,-0.902) 9(3.875,-0.902)
CON_RJ45-14_LPJG16314A4NL_S_R_T_13-6
  round 3.073 hole 3.2 unplated: (0,-8.89) (11.43,-8.89)
  rect 1.6x1.6 hole 0.914: 1(0,0)
  round 1.6 hole 0.914: 2(1.27,-2.54) 3(2.54,0) 4(3.81,-2.54) 5(5.08,0) 6(6.35,-2.54) 7(7.62,0) 8(8.89,-2.54) 9(10.16,0) 10(11.43,-2.54)
  round 1.702 hole 1.016: 11(12.44,-11.43) 12(12.44,-13.462) 13(-1.01,-11.43) 14(-1.01,-13.462)
  round 2.362 hole 1.676: 15(-2.032,-5.842) 16(13.462,-5.842)
CON_USBC24_6327233_S_R_S_3-1
  rect 0.305x1.194 smd: A1(-2.75,5.815) A2(-2.25,5.815) A3(-1.75,5.815) A4(-1.25,5.815) A5(-0.75,5.815) A6(-0.25,5.815) A7(0.25,5.815) A8(0.75,5.815) A9(1.25,5.815) A10(1.75,5.815) A11(2.25,5.815) A12(2.75,5.815)
  round 0.66 hole 0.406: B1(2.8,4.565) B2(2.4,3.865) B3(1.6,3.865) B4(1.2,4.565) B5(0.8,3.865) B6(0.4,4.565) B7(-0.4,4.565) B8(-0.8,3.865) B9(-1.2,4.565) B10(-1.6,3.865) B11(-2.4,3.865) B12(-2.8,4.565) G1(-2,4.565) G2(2,4.565)
  oval 0.991x1.6 hole 0.61x1.219: SH1(-4.27,3.415) SH2(4.27,3.415) SH3(-4.27,-1.315) SH4(4.27,-1.315)
  rect 0.203x0.991 smd: SH5(0,1.235) SH6(0,-1.865)
DIO_DFN0201_0-4
  rect 0.229x0.381 smd: 1(-0.22,0) 2(0.22,0)
DIO_SMB_2-7
  rect 2.261x2.159 smd: 1(-2.2,0) 2(2.2,0)
EMIFIL_BLM18B_0603_0-7
  rect 1.194x1.092 smd: 1(-0.85,0) 2(0.85,0)
HDR_1X2_61300211121_S_T_8-6
  rect 1.803x1.803 hole 1.118: 1(0,0)
  round 1.803 hole 1.118: 2(-2.54,0)
HDR_1X3_100_S_T
  rect 1.803x1.803 hole 1.118: 1(0,0)
  round 1.803 hole 1.118: 2(-2.54,0) 3(-5.08,0)
HDR_1X5_61300511121_S_T_8-6
  rect 1.803x1.803 hole 1.118: 1(0,0)
  round 1.803 hole 1.118: 2(-2.54,0) 3(-5.08,0) 4(-7.62,0) 5(-10.16,0)
HDR_1X6_61300611121_S_T_8-6
  rect 1.803x1.803 hole 1.118: 1(0,0)
  round 1.803 hole 1.118: 2(-2.54,0) 3(-5.08,0) 4(-7.62,0) 5(-10.16,0) 6(-12.7,0)
